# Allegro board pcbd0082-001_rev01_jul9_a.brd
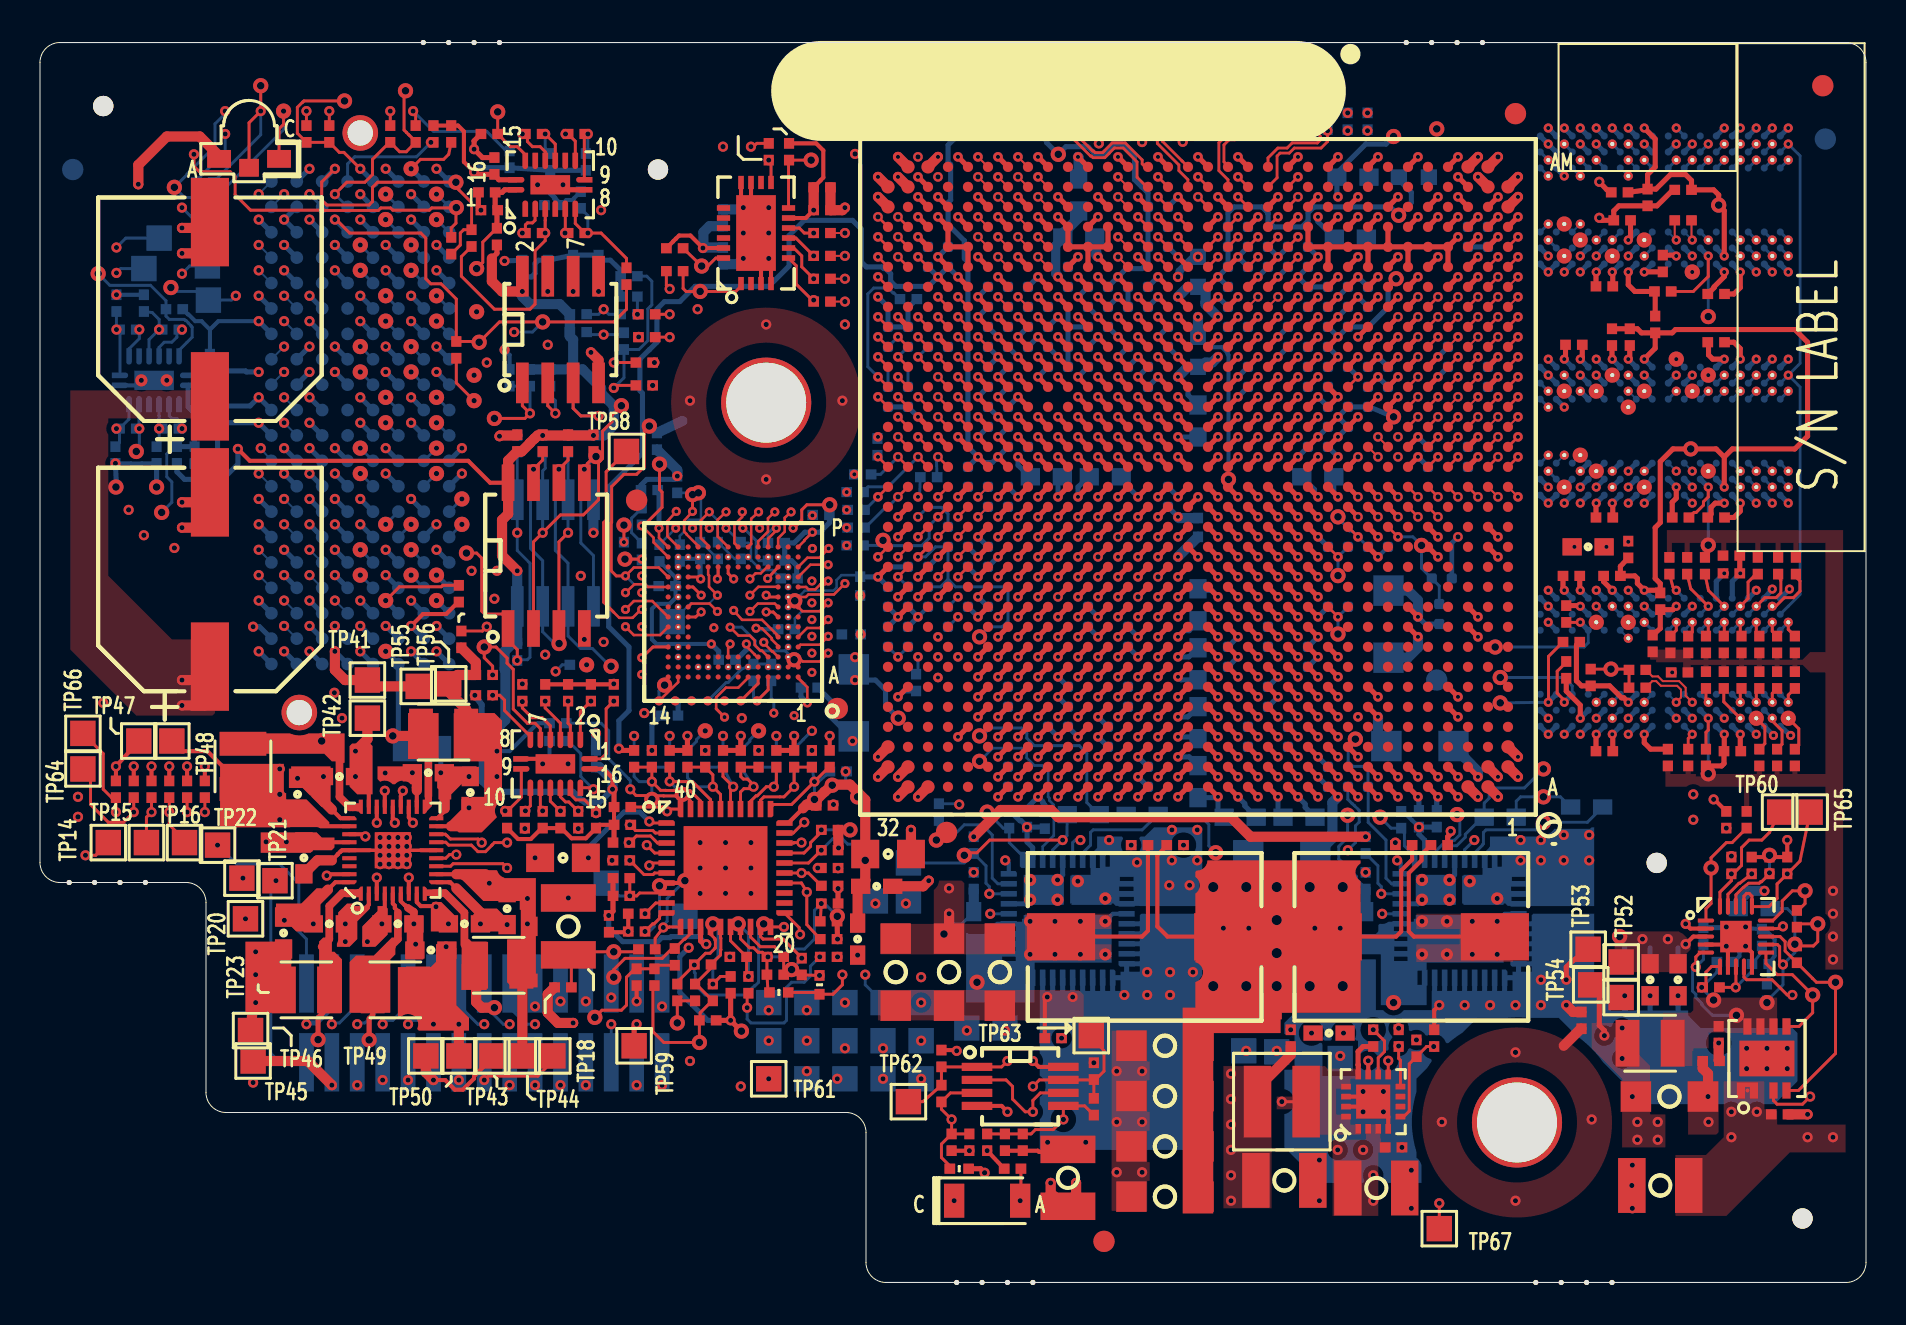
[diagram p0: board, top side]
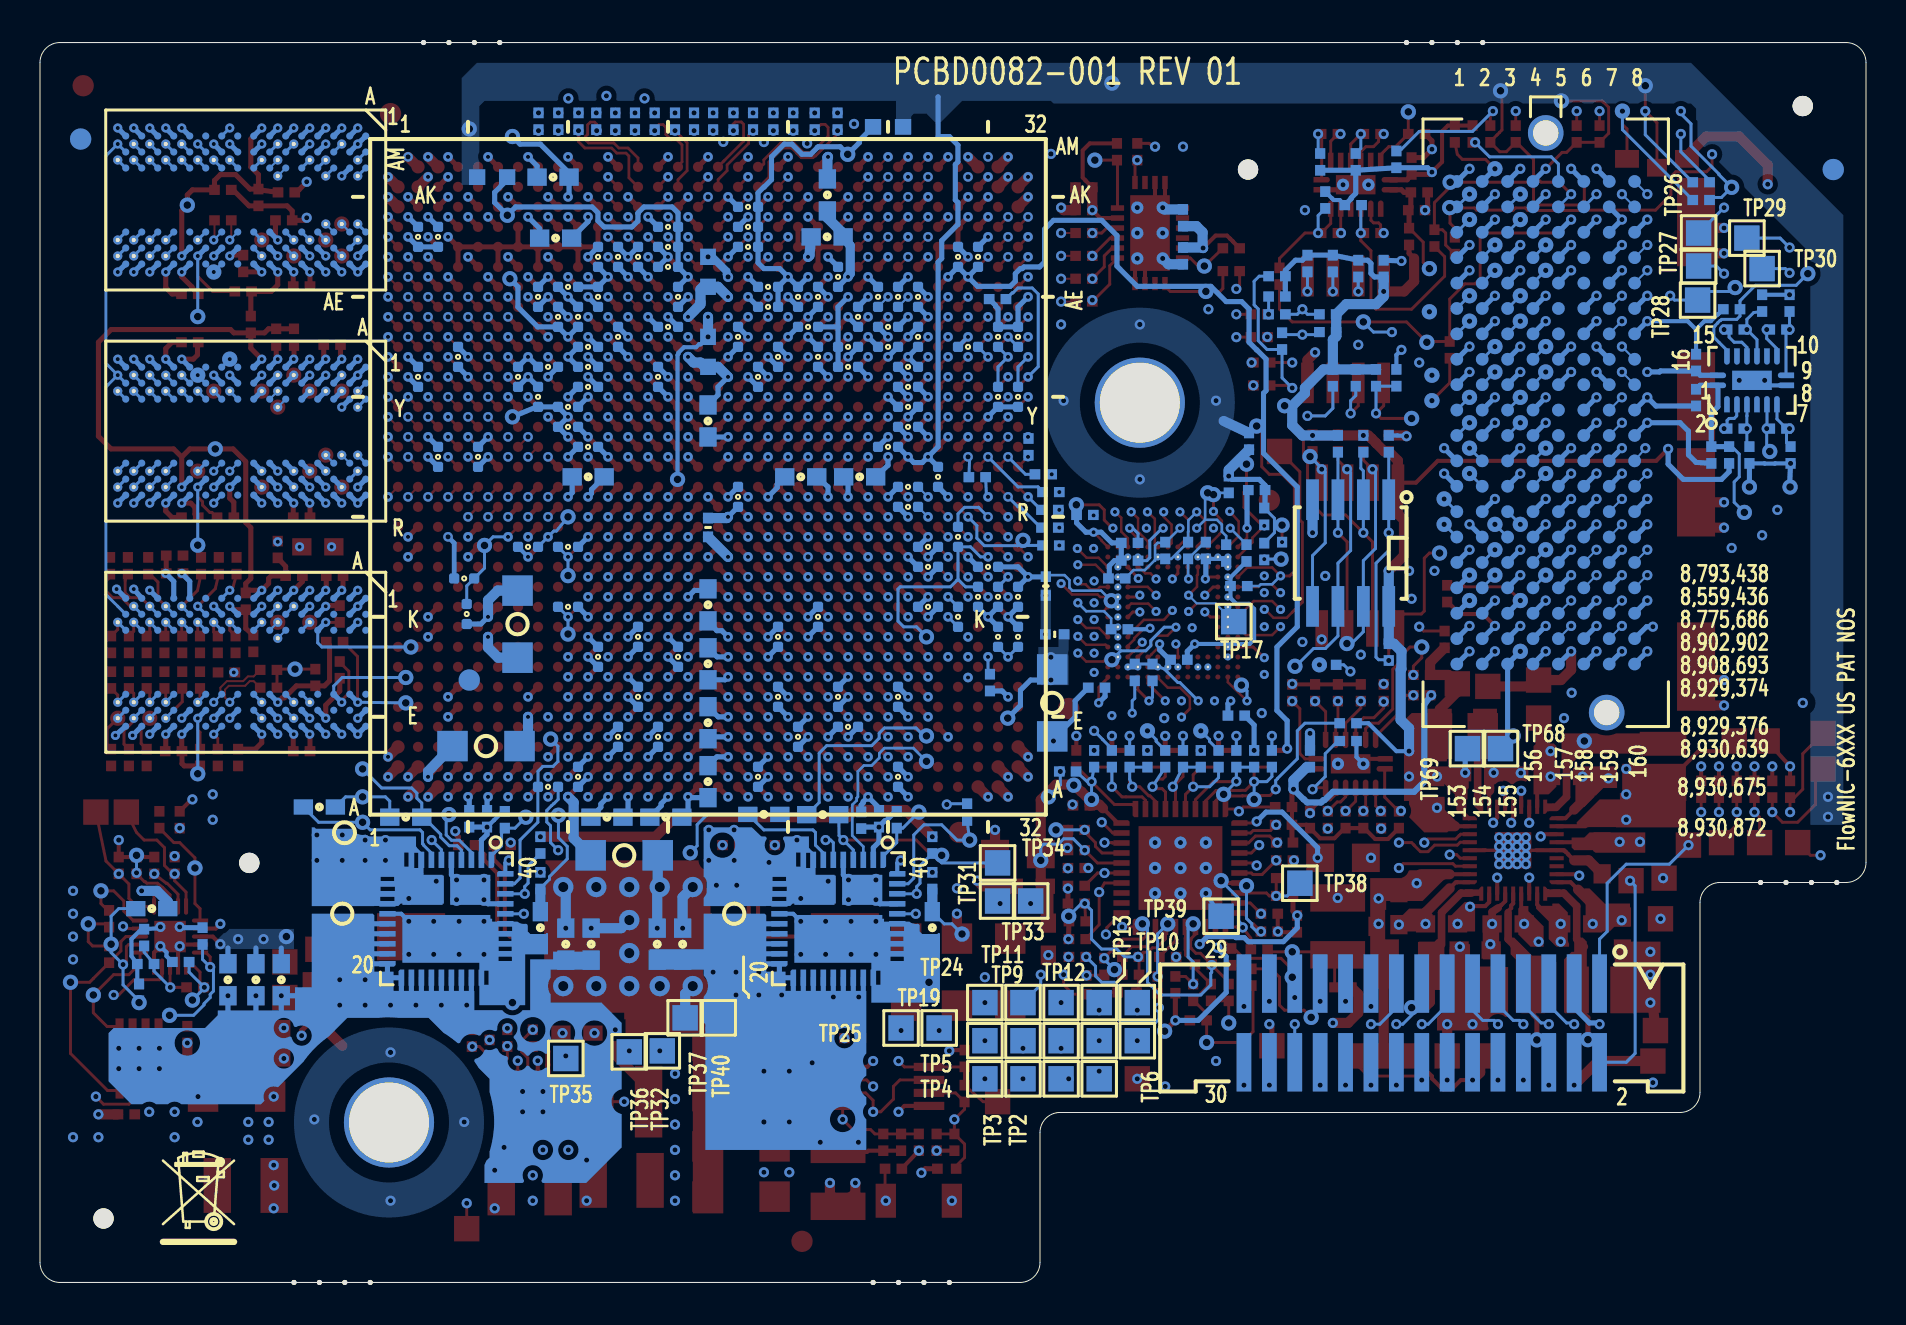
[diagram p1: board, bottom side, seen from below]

Outline 91.3 x 62 mm; copper layers: TOP, 02_GND, 03_SIG, 04_SIG, 05_GND, 06_PWR1, 07_SIG, 08_SIG, 09_GND, BOTTOM. Coordinates in mm from the lower left corner of the outline.
Outline path: 0,61 arc(0.29,61.71) 1,62 90.3,62 arc(91.01,61.71) 91.3,61 91.3,1 arc(91.01,0.29) 90.3,0 42.3,0 arc(41.59,0.29) 41.3,1 41.3,7.5 arc(41.01,8.21) 40.3,8.5 9.3,8.5 arc(8.59,8.79) 8.3,9.5 8.3,19 arc(8.01,19.71) 7.3,20 1,20 arc(0.29,20.29) 0,21 0,61

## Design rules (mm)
net group 100_OHM_DIFF_SPACE: nets PCIE0_REFCLK_N PCIE0_REFCLK_P
net group NFP_CLK_REF_: nets NFP_CLK_REF_N NFP_CLK_REF_P
net group NFP_SERDES012_SYSCLK_IN_: nets NFP_SERDES012_SYSCLK_IN_N NFP_SERDES012_SYSCLK_IN_P
net group NFP_VDD_CORE_SENSE_VDD: nets NFP_VDD_CORE_SENSE_VDD NFP_VDD_CORE_SENSE_VSS
net group 15MIL_EMPTY_SPACE_CLK: nets _NC_SPI3_SCK _NFP_ARM_SPI_FLASH_SCK _NFP_CFG_SPI_FLASH_SCK _NFP_SPI2_SCK _PSU_I2C_SCL CNTRL_SPI_SCK CPLD_PGRM_JTAG_TCK CPLD_PGRM_JTAG_TMS CPLD_SMBUS_SCL DEBUG_CPLD_PGRM_JTAG_TCK DEBUG_CPLD_PGRM_JTAG_TMS MUX_NFP_GPIO0_NWK0_I2C_SCL MUX_NFP_GPIO2_NWK1_I2C_SCL MUX_NFP_SMBUS_SCL NFP_ARM_SPI_FLASH_SCK NFP_CFG_SPI_FLASH_SCK NFP_CPLD_PRGM_JTAG_TCK NFP_CPLD_PRGM_JTAG_TMS NFP_JTAG_ARM_TCK NFP_JTAG_ARM_TMS NFP_SMBUS_SCL NFP_SPI2_SCK NWK0_I2C_SCL NWK1_I2C_SCL PGRM_JTAG_TCK PGRM_JTAG_TMS PSU_I2C_SCL SMBUS_SCL
net group 40_OHM_SE_SPACE: nets DDR0_32A_DRAMRST_L
net group 100_OHM_DIFF_PH: nets _NC_156M_N _NC_156M_P _NC_NFP_SERDES0_TX1_N _NC_NFP_SERDES0_TX1_P _NC_NFP_SERDES0_TX2_N _NC_NFP_SERDES0_TX2_P _NC_NFP_SERDES0_TX3_N _NC_NFP_SERDES0_TX3_P _NC_NFP_SERDES2_TX1_N _NC_NFP_SERDES2_TX1_P
net group POWER_PH: nets DDR_1.8V VDD_1.2V VDD_1.8V VDDA_DDR0_32B VDDA_SERDES VDDA_TS0 VDDAH_PCIE0 VDDAH_SERDES
net group PROP_DELAY_BYTE_0: nets DDR0_32A_DM0 DDR0_32A_DQ0 DDR0_32A_DQ1 DDR0_32A_DQ2 DDR0_32A_DQ3 DDR0_32A_DQ4 DDR0_32A_DQ5 DDR0_32A_DQ6 DDR0_32A_DQ7 DDR0_32A_DQS0_P
net group PROP_DELAY_BYTE_1: nets DDR0_32A_DM1 DDR0_32A_DQ8 DDR0_32A_DQ9 DDR0_32A_DQ10 DDR0_32A_DQ11 DDR0_32A_DQ12 DDR0_32A_DQ13 DDR0_32A_DQ14 DDR0_32A_DQ15 DDR0_32A_DQS1_P
net group PROP_DELAY_BYTE_2: nets DDR0_32A_DM2 DDR0_32A_DQ16 DDR0_32A_DQ17 DDR0_32A_DQ18 DDR0_32A_DQ19 DDR0_32A_DQ20 DDR0_32A_DQ21 DDR0_32A_DQ22 DDR0_32A_DQ23 DDR0_32A_DQS2_P
net group PROP_DELAY_BYTE_3: nets DDR0_32A_DM3 DDR0_32A_DQ24 DDR0_32A_DQ25 DDR0_32A_DQ26 DDR0_32A_DQ27 DDR0_32A_DQ28 DDR0_32A_DQ29 DDR0_32A_DQ30 DDR0_32A_DQ31 DDR0_32A_DQS3_P
net group PROP_DELAY_BYTE_CB: nets DDR0_32A_CB0 DDR0_32A_CB1 DDR0_32A_CB2 DDR0_32A_CB3 DDR0_32A_CB4 DDR0_32A_CB5 DDR0_32A_CB6 DDR0_32A_CB7 DDR0_32A_DM4 DDR0_32A_DQS4_P
net group PWR_SENSE_20MIL_DIFF_PH: nets NFP_VDD_CORE_ISEN1_N NFP_VDD_CORE_ISEN1_P NFP_VDD_CORE_ISEN2_N NFP_VDD_CORE_ISEN2_P
net group PWR_SENSE_SPACE: nets NFP_VDD_CORE_IMON NFP_VDD_CORE_TCOMPA NFP_VDD_CORE_TCOMPB

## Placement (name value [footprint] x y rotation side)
C1  22UF  [C_0603]  63.89 40.28 90 bottom
C2  22UF  [C_0603]  77.41 36.78 90 top
C3  22UF  [C_0603]  57.9 30.94 0 bottom
C4  22UF  [C_0603]  50.32 40.28 270 bottom
C5  22UF  [C_0603]  57.9 43.08 180 bottom
C7  22UF  [C_0603]  57.9 33.88 0 bottom
C8  10UF  [C_0402#2]  61.4 32.28 180 bottom
C9  10UF  [C_0402#2]  54.4 32.28 180 bottom
C10  22UF  [C_0603]  53.26 40.28 270 bottom
C11  22UF  [C_0603]  60.01 23.26 90 bottom
C12  22UF  [C_0603]  62.95 23.26 270 bottom
C13  22UF  [C_0603]  57.9 27.99 180 bottom
C14  22UF  [C_0603]  57.9 25.04 180 bottom
C15  22UF  [C_0603]  65.01 16.91 180 bottom
C16  22UF  [C_0603]  63.74 16.91 180 bottom
C17  22UF  [C_0603]  59.17 16.91 180 bottom
C18  22UF  [C_0603]  60.44 16.91 180 bottom
C19  22UF  [C_0603]  19.55 16.62 270 top
C20  22UF  [C_0603]  12.88 24.41 180 top
C21  22UF  [C_0603]  23.36 18.69 0 top
C22  22UF  [C_0603]  12.18 17.47 180 top
C23  22UF  [C_0603]  21.51 24.5 180 top
C24  0.01UF  [C_0402]  39.1 54.76 90 top
C25  0.01UF  [C_0402#2]  46.9 33.78 270 bottom
C26  0.01UF  [C_0402#2]  46.9 35.78 270 bottom
C27  0.01UF  [C_0402#2]  46.9 36.78 270 bottom
C28  0.01UF  [C_0402#2]  56.4 47.28 180 bottom
C29  0.01UF  [C_0402#2]  63.9 41.78 90 bottom
C30  0.01UF  [C_0402#2]  59.4 49.28 180 bottom
C31  0.01UF  [C_0402]  86.02 15.92 270 bottom
C32  0.22UF  [C_0603]  73.01 23.26 270 bottom
C33  0.22UF  [C_0603]  52.16 23.39 270 bottom
C34  6800PF  [C_0402]  36.77 15.39 90 top
C35  6800PF  [C_0402]  36.77 16.28 90 top
C36  10UF  [C_0402]  34.15 53.24 0 bottom
C37  10UF  [C_0402#2]  63.4 49.28 180 bottom
C38  10UF  [C_0402#2]  59.9 51.78 270 bottom
C39  10UF  [C_0402#2]  59.9 52.78 270 bottom
C40  10UF  [C_0402#2]  51.4 50.28 0 bottom
C41  10UF  [C_0402#2]  55.9 53.78 270 bottom
C42  10UF  [C_0402#2]  55.9 52.78 270 bottom
C43  10UF  [C_0402#2]  54.9 48.78 270 bottom
C44  10UF  [C_0402#2]  56.4 39.28 0 bottom
C46  1000PF  [C_0402]  46.68 20.09 0 bottom
C47  1000PF  [C_0402]  66.28 20.09 0 bottom
C48  1000PF  [C_0402]  31.86 14.5 0 top
C49  1000PF  [C_0402]  33.64 14.5 180 top
C50  1000PF  [C_0402]  34.91 16.28 270 top
C51  1000PF  [C_0402]  83.55 11.07 270 top
C52  68PF  [C_0402]  33.13 15.9 90 top
C57  100UF  [C_1206]  40.69 28.98 180 bottom
C58  100UF  [C_1206]  62.09 21.36 270 bottom
C59  100UF  [C_1206]  47.99 15.52 0 top
C60  100UF  [C_1206]  45.45 15.52 0 top
C61  100UF  [C_1206]  42.79 15.52 0 top
C62  100UF  [C_1206]  56.25 11.83 270 top
C63  100UF  [C_1206]  56.25 9.32 270 top
C64  100UF  [C_1206]  56.25 6.81 270 top
C65  100UF  [C_1206]  56.25 4.29 270 top
C66  100UF  [C_1206]  81.47 9.29 90 top
C67  100UF  [C_1206]  67.42 32.92 0 bottom
C68  100UF  [C_1206]  69 26.82 270 bottom
C71  8.2PF  [C_0402]  82.16 53.11 90 top
C74  4.7UF  [C_0402#2]  42.4 34.28 180 bottom
C76  4.7UF  [C_0402#2]  71.4 41.28 0 bottom
C77  4.7UF  [C_0402#2]  54.4 46.28 180 bottom
C78  4.7UF  [C_0402#2]  59.9 47.78 90 bottom
C79  4.7UF  [C_0402#2]  48.4 25.28 180 bottom
C80  4.7UF  [C_0402#2]  64.4 25.28 180 bottom
C81  680PF  [C_0402]  29.83 15.26 0 top
C82  1500PF  [C_0402]  28.45 17.93 0 top
C83  0.1UF  [C_0402]  39.1 53.62 90 top
C84  0.1UF  [C_0402]  34.15 51.33 180 bottom
C85  0.1UF  [C_0402]  24.12 50.7 0 bottom
C86  0.1UF  [C_0402#2]  43.9 35.78 270 bottom
C87  0.1UF  [C_0402]  23.86 41.97 180 top
C89  0.1UF  [C_0402#2]  62.4 51.28 0 bottom
C90  0.1UF  [C_0402#2]  61.4 51.28 0 bottom
C91  0.1UF  [C_0402#2]  59.9 50.78 270 bottom
C92  0.1UF  [C_0402#2]  50.4 48.28 180 bottom
C93  0.1UF  [C_0402#2]  50.9 46.78 90 bottom
C94  0.1UF  [C_0402#2]  52.9 47.78 270 bottom
C101  0.1UF  [C_0402#2]  55.9 51.78 270 bottom
C102  0.1UF  [C_0402#2]  54.9 49.78 270 bottom
C103  0.1UF  [C_0402#2]  53.4 49.28 180 bottom
C105  0.1UF  [C_0402]  77.53 30.25 0 top
C108  0.1UF  [C_0402]  84.57 36.35 270 top
C109  0.1UF  [C_0402]  81.98 30.5 270 top
C110  0.1UF  [C_0402]  80.63 31.95 180 top
C111  0.1UF  [C_0402]  81.39 26.25 0 top
C116  0.1UF  [C_0402#2]  65.4 48.28 0 bottom
C118  0.1UF  [C_0402]  31.48 28.34 90 bottom
C119  0.1UF  [C_0402]  39.05 38.38 90 bottom
C120  0.1UF  [C_0402]  30.47 39.62 90 bottom
C121  0.1UF  [C_0402]  38.47 29.74 270 bottom
C122  0.1UF  [C_0402]  34.35 31.14 90 bottom
C123  0.1UF  [C_0402]  27.8 26.19 0 bottom
C124  0.1UF  [C_0402]  39.23 23.85 90 top
C125  0.1UF  [C_0402]  29.07 20.22 90 top
C126  0.1UF  [C_0402]  67.68 6.75 90 top
C127  0.1UF  [C_0402]  66.66 12.22 0 top
C128  0.1UF  [C_0402]  84.26 16.03 270 bottom
C129  0.1UF  [C_0402]  87.85 16.41 0 top
C130  0.1UF  [C_0402]  86.98 8.41 90 top
C131  10UF  [C_0603]  14.47 17.93 270 top
C132  10UF  [C_0603]  21.22 17.93 90 top
C133  10UF  [C_0603]  17.89 17.93 90 top
C134  10UF  [C_0603]  14.97 25.3 270 top
C135  10UF  [C_0603]  13.2 21.23 0 top
C136  10UF  [C_0603]  81.9 15.14 180 bottom
C137  10UF  [C_0603]  80.51 15.14 180 bottom
C138  10UF  [C_0603]  81.9 15.14 0 top
C139  10UF  [C_0603]  80.51 15.14 0 top
C140  10UF  [C_0603]  79.24 15.14 180 bottom
C141  10UF  [C_0603]  19.42 25.49 90 top
C142  4.7UF  [C_0805]  26.15 21.23 270 top
C143  4.7UF  [C_0805]  42.41 21.42 90 top
C144  4.7UF  [C_1210]  26.42 17.8 90 top
C145  0.22UF  [C_0402]  57.65 58.06 0 bottom
C146  0.22UF  [C_0402]  58.6 58.06 0 bottom
C147  0.22UF  [C_0402]  56.63 58.06 0 bottom
C148  0.22UF  [C_0402]  55.65 58.06 0 bottom
C149  0.22UF  [C_0402]  54.63 58.06 0 bottom
C150  0.22UF  [C_0402]  53.64 58.06 0 bottom
C151  0.22UF  [C_0402]  52.57 58.06 0 bottom
C152  0.22UF  [C_0402]  51.42 58.06 0 bottom
C153  0.22UF  [C_0402]  65.38 58.06 0 bottom
C154  0.22UF  [C_0402]  66.38 58.06 0 bottom
C155  0.22UF  [C_0402]  63.49 58.06 0 bottom
C156  0.22UF  [C_0402]  64.38 58.06 0 bottom
C157  0.22UF  [C_0402]  62.54 58.06 0 bottom
C158  0.22UF  [C_0402]  61.55 58.06 0 bottom
C159  0.22UF  [C_0402]  60.57 58.06 0 bottom
C160  0.22UF  [C_0402]  59.55 58.06 0 bottom
C161  0.22UF  [C_0402#2]  60.4 45.28 180 bottom
C162  0.22UF  [C_0402#2]  55.4 45.28 180 bottom
C163  0.22UF  [C_0402#2]  59.4 31.28 180 bottom
C165  0.22UF  [C_0402]  83.17 17.32 0 bottom
C166  2.2UF  [C_0402#2]  62.4 47.28 180 bottom
C167  2.2UF  [C_0402#2]  48.4 29.28 180 bottom
C168  2.2UF  [C_0402#2]  62.4 27.28 180 bottom
C169  0.47UF  [C_0402#2]  63.4 51.28 0 bottom
C170  0.47UF  [C_0402#2]  64.9 49.78 270 bottom
C171  0.47UF  [C_0402#2]  52.4 49.28 180 bottom
C172  0.47UF  [C_0402#2]  50.9 45.78 90 bottom
C173  0.47UF  [C_0402#2]  55.4 25.28 180 bottom
C174  0.47UF  [C_0402#2]  53.4 27.28 180 bottom
C175  0.47UF  [C_0402#2]  52.4 33.28 0 bottom
C176  0.47UF  [C_0402#2]  50.9 27.78 90 bottom
C177  0.47UF  [C_0402#2]  63.4 31.28 180 bottom
C178  0.47UF  [C_0402#2]  52.4 46.28 180 bottom
C179  22UF  [C_1210]  76.19 18.44 270 bottom
C180  22UF  [C_1210]  56.59 18.44 270 bottom
C181  22UF  [C_1210]  62.22 5.1 0 top
C182  22UF  [C_1210]  51.4 5.23 90 top
C183  22UF  [C_1210]  66.81 4.72 0 top
C184  22UF  [C_1210]  81.01 4.85 180 top
C186  1UF  [C_0402#2]  63.9 45.78 90 bottom
C187  1UF  [C_0402#2]  64.4 48.28 0 bottom
C190  1UF  [C_0402#2]  69.4 41.28 0 bottom
C191  1UF  [C_0402#2]  72.4 52.28 0 bottom
C192  1UF  [C_0402#2]  72.4 45.28 0 bottom
C193  1UF  [C_0402#2]  70.4 46.28 0 bottom
C194  1UF  [C_0402#2]  67.4 45.28 0 bottom
C195  1UF  [C_0402#2]  66.4 49.28 0 bottom
C196  1UF  [C_0402#2]  64.9 42.78 90 bottom
C197  1UF  [C_0402#2]  54.4 29.28 180 bottom
C198  1UF  [C_0402#2]  60.4 27.28 180 bottom
C199  1UF  [C_0402#2]  61.4 29.28 180 bottom
C200  1UF  [C_0402#2]  51.4 29.28 180 bottom
C201  1UF  [C_0402]  68.95 23.19 0 bottom
C202  1UF  [C_0402]  69.84 23.19 0 bottom
C203  1UF  [C_0402]  49.35 23.19 0 bottom
C204  1UF  [C_0402]  50.24 23.11 0 bottom
C205  1UF  [C_0402]  86.35 14.5 0 bottom
C206  1UF  [C_0402]  80.38 54.25 0 top
C211  1UF  [C_0402]  83.81 49.43 270 top
C212  1UF  [C_0402]  78.22 49.81 90 top
C213  1UF  [C_0402]  81.14 50.95 180 top
C214  1UF  [C_0402]  79.11 53.11 270 top
C215  1UF  [C_0402]  83.81 38.25 270 top
C216  1UF  [C_0402]  83.81 47.01 270 top
C217  1UF  [C_0402]  76.57 35.33 90 top
C218  1UF  [C_0402]  84.62 26.57 270 top
C219  1UF  [C_0402]  78.22 26.57 90 top
C220  1UF  [C_0402]  84.57 35.46 270 top
C242  220UF  [SMC_ECE-CAP_10P2MM]  8.5 35.15 180 top
C243  220UF  [SMC_ECE-CAP_10P2MM]  8.5 48.66 180 top
C248  0.1UF  [C_0402]  46.47 7.01 0 top
C249  0.1UF  [C_0402]  49.14 7.01 0 top
C263  1UF  [C_0402]  80.76 47.9 180 top
C264  1UF  [C_0402]  81.01 34.06 0 top
C265  1UF  [C_0402]  76.7 46.89 90 top
C266  1UF  [C_0402]  78.22 38.25 90 top
C268  4.7UF  [C_0402#2]  47.9 42.78 270 bottom
C269  4.7UF  [C_0402#2]  48.9 41.78 270 bottom
C270  4.7UF  [C_0402#2]  45.4 51.28 0 bottom
C271  4.7UF  [C_0402#2]  47.9 43.78 270 bottom
C272  0.1UF  [C_0402#2]  47.9 44.78 90 bottom
C273  0.1UF  [C_0402#2]  46.4 40.28 180 bottom
C274  0.1UF  [C_0402#2]  44.4 51.28 0 bottom
C275  0.1UF  [C_0402#2]  47.9 45.78 270 bottom
C276  0.1UF  [C_0402#2]  47.4 47.28 0 bottom
C277  0.1UF  [C_0402#2]  47.4 49.28 0 bottom
C278  22UF  [C_0603]  65.52 52.22 270 bottom
C279  22UF  [C_0603]  65.65 55.27 270 bottom
C280  22UF  [C_0603]  51.93 54.38 0 bottom
C281  22UF  [C_0603]  51.94 52.28 270 bottom
C282  4.7UF  [C_0402]  22.34 54.51 270 top
C283  4.7UF  [C_0402]  8.5 44.25 180 bottom
C284  0.1UF  [C_0402]  22.72 55.83 180 top
C285  0.1UF  [C_0402]  8.5 46 0 bottom
D5  LL4148  [SOD80]  47.36 4.09 0 top
DS1  *  [APBVDA3020CGKSYKC]  10.45 56.18 180 top
J4  VAL  [CON_SAM_SEAM-20-03P5-S-08-2-A-K]  16.01 42.99 90 bottom
J5  *  [HDR_2X15_1000_240_50_SMT_SHF]  22.21 12.98 0 bottom
L1  120_100MHZ  [0603]  68.69 55.27 180 bottom
L2  120_100MHZ  [0603]  57.9 50.53 90 bottom
L3  120_100MHZ  [0603]  57.9 46.53 90 bottom
L7  0.05OHMDC_1A  [0402]  57.9 37.75 90 bottom
L9  1.0UH  [IND_SMT_2520]  80.51 11.96 180 top
L10  2.2UH  [IND_SMT_2520]  10.15 25.8 90 top
L11  2.2UH  [IND_SMT_2520]  13.32 14.63 0 top
L12  2.2UH  [IND_SMT_2520]  22.94 15.86 0 top
L13  60MOHM_1.7A  [0402]  40.56 32.41 180 bottom
L14  60MOHM_1.7A  [0402]  41.01 34.82 270 bottom
L15  120_100MHZ  [0603]  48.9 57.78 0 bottom
L17  300NH  [IND_295_425_SMT_SLC1175]  68.57 17.28 270 top
L18  300NH  [IND_295_425_SMT_SLC1175]  55.23 17.28 90 top
L19  1.0UH  [IND_SMT_2520]  17.77 14.63 180 top
L20  1.0UH  [IND_SMT_2520]  20.18 27.52 0 top
L21  3.3UH  [IND_SMT_4X4X2P1]  62.09 9.04 180 top
NOREF  -  []  91.3 -7.92 90 top
NOREF#2  -  []  -395.74 -176.46 0 top
NOREF#3  -  [unnamed#2]  53.2 2.06 0 top
NOREF#4  -  []  -0.01 69.92 0 top
NOREF#5  -  []  1 62 0 top
NOREF#6  -  []  30.54 23.43 0 top
NOREF#7  -  []  3.16 58.82 0 top
NOREF#8  -  []  3.16 58.82 0 top
NOREF#9  -  [unnamed#2]  3.16 58.82 0 top
NOREF#10  -  []  0 -7.92 0 top
NOREF#11  -  []  1.45 -17.39 0 top
NOREF#12  -  [unnamed#2]  80.84 20.98 0 top
NOREF#13  -  [unnamed#2]  89.14 59.84 0 top
NOREF#14  -  [unnamed#3]  91.3 62 0 top
NOREF#15  -  [unnamed#2]  30.9 55.65 0 top
NOREF#16  -  []  101.59 139.47 0 top
NOREF#17  -  [unnamed#2]  88.13 3.2 0 top
NOREF#18  -  []  90.3 0 90 top
NOREF#19  -  []  -395.74 -176.46 0 top
NOREF#20  -  [unnamed#4]  49.64 0 270 bottom
NOREF#21  -  [unnamed#4]  19.16 62 90 bottom
NOREF#22  -  [unnamed#4]  68.31 62 90 bottom
NOREF#23  -  [unnamed#4]  5.27 20 270 bottom
NOREF#24  -  [unnamed#2]  89.27 57.17 180 bottom
NOREF#25  -  [unnamed#2]  1.64 55.65 180 bottom
NOREF#26  -  []  58.53 99.72 180 bottom
NOREF#27  -  [unnamed#2]  69.84 30.12 180 bottom
NOREF#28  -  [unnamed#4]  78.6 0 270 bottom
Q1  *  [SON8_130_25P6_EP_Q3D]  86.35 11.2 90 top
R1  121K  [R_0402]  29.83 18.44 90 top
R2  100K  [R_0603]  64.45 12.47 90 top
R3  332K  [R_0402]  30.34 16.66 90 top
R4  30.1K  [R_0402]  86.09 17.25 180 bottom
R7  36.0  [R_0402]  79.87 29.74 270 top
R8  36.0  [R_0402]  79.87 30.63 270 top
R13  82K  [0402]  36.94 14.5 180 top
R14  4.75K  [R_0402]  37.45 56.54 0 top
R15  4.75K  [R_0402]  31.74 51.71 90 top
R16  4.75K  [R_0402#2]  44.9 46.78 270 bottom
R18  4.75K  [R_0402]  23.48 45.24 0 bottom
R19  4.75K  [R_0402#2]  43.4 34.28 0 bottom
R20  4.75K  [R_0402]  25.13 41.93 180 bottom
R21  4.75K  [R_0402]  25.13 41.97 0 top
R22  4.75K  [R_0402]  26.4 41.97 0 top
R23  4.75K  [R_0402]  27.67 41.97 0 top
R24  4.75K  [R_0402]  25.51 45.24 180 bottom
R25  4.75K  [R_0402]  25.39 50.7 180 bottom
R26  4.75K  [R_0402]  26.66 50.95 180 bottom
R27  4.75K  [R_0402]  27.93 50.95 180 bottom
R28  4.75K  [R_0402]  23.86 31.52 180 bottom
R29  4.75K  [R_0402]  26.4 41.93 180 bottom
R30  4.75K  [R_0402]  24.5 45.24 180 bottom
R31  4.75K  [R_0402]  26.66 45.24 180 bottom
R32  4.75K  [R_0402]  23.86 41.93 0 bottom
R34  4.75K  [R_0402]  21.07 32.15 0 top
R41  4.75K  [R_0402#2]  43.4 47.28 180 bottom
R42  4.75K  [R_0402#2]  42.4 47.28 180 bottom
R43  4.75K  [R_0402]  29.45 49.3 270 bottom
R44  4.75K  [R_0402]  26.91 48.41 270 bottom
R45  4.75K  [R_0402#2]  42.4 44.28 180 bottom
R46  4.75K  [R_0402#2]  43.4 44.28 180 bottom
R47  4.75K  [R_0402]  30.09 36.55 0 bottom
R48  4.75K  [R_0402]  37.33 32.66 270 bottom
R49  4.75K  [R_0402]  35.04 36.6 180 bottom
R50  4.75K  [R_0402]  37.46 35.2 90 bottom
R52  4.75K  [R_0402]  33.01 36.6 0 bottom
R53  4.75K  [R_0402]  31.99 36.47 0 bottom
R54  4.75K  [R_0402]  31.86 39.9 0 bottom
R55  4.75K  [R_0402]  33.9 36.6 0 bottom
R56  4.75K  [R_0402]  30.09 38.3 0 bottom
R57  4.75K  [R_0402]  30.98 36.47 180 bottom
R58  4.75K  [R_0402]  31.36 34.82 270 bottom
R59  4.75K  [R_0402]  25.9 27.07 90 bottom
R60  4.75K  [R_0402]  28.69 29.49 180 top
R61  4.75K  [R_0402]  26.02 23.14 180 top
R62  4.75K  [R_0402]  23.36 23.14 180 top
R63  4.75K  [R_0402]  22.21 29.36 90 top
R64  4.75K  [R_0402]  26.4 29.49 180 top
R65  4.75K  [R_0402]  27.55 29.49 180 top
R66  4.75K  [R_0402]  26.91 23.14 180 top
R67  4.75K  [R_0402]  24.24 23.14 180 top
R68  4.75K  [R_0402]  22.21 30.38 90 top
R69  4.75K  [R_0402]  27.8 23.14 180 top
R70  4.75K  [R_0402]  25.13 23.14 180 top
R71  4.75K  [R_0402]  24.12 29.49 0 top
R72  4.75K  [R_0402]  25.26 29.49 180 top
R73  4.75K  [R_0402]  20.56 57.43 0 top
R74  4.75K  [R_0402]  48.46 23.14 180 bottom
R75  4.75K  [R_0402]  66.28 21.87 0 bottom
R76  4.75K  [R_0402]  46.68 21.87 0 bottom
R77  4.75K  [R_0402]  36.82 26.19 180 top
R78  4.75K  [R_0402]  37.71 26.19 180 top
R79  4.75K  [R_0402]  39.48 26.19 180 top
R80  4.75K  [R_0402]  38.6 26.19 0 top
R81  4.75K  [R_0402]  38.6 26.19 180 bottom
R82  4.75K  [R_0402]  35.93 26.19 180 bottom
R83  4.75K  [R_0402]  30.59 26.19 0 top
R84  4.75K  [R_0402]  29.71 26.19 180 top
R85  4.75K  [R_0402]  29.07 21.99 270 top
R86  4.75K  [R_0402]  29.12 22.88 270 top
R87  4.75K  [R_0402]  29.12 23.77 270 top
R88  4.75K  [R_0402]  29.07 21.11 90 top
R89  4.75K  [R_0402]  25.9 27.96 90 bottom
R90  4.75K  [R_0402]  35.04 26.19 180 top
R91  4.75K  [R_0402]  35.93 26.19 0 top
R92  4.75K  [R_0402]  31.48 26.19 180 top
R93  4.75K  [R_0402]  32.37 26.19 180 top
R94  4.75K  [R_0402]  34.15 26.19 180 top
R95  4.75K  [R_0402]  33.26 26.19 180 bottom
R96  4.75K  [R_0402]  33.26 26.19 0 top
R97  4.75K  [R_0402]  30.59 26.19 180 bottom
R98  4.75K  [R_0402]  7.35 24.66 180 top
R99  4.75K  [R_0402]  67.93 12.22 180 top
R100  4.75K  [R_0402]  4.69 24.66 180 top
R101  4.75K  [R_0402]  45.07 11.2 0 top
R102  4.75K  [R_0402]  52.69 10.56 0 top
R103  4.75K  [R_0402]  3.8 24.66 0 top
R104  4.75K  [R_0402]  8.24 24.66 180 top
R105  4.75K  [R_0402]  87.36 20.85 0 top
R106  4.75K  [R_0402]  84.57 20.85 180 top
R107  40.2K  [R_0402]  86.47 20.85 0 top
R108  2.2  [R_0402]  87.85 18.18 0 top
R109  2.2  [R_0402]  83.93 12.39 180 top
R110  10  [R_0402]  39.48 20.72 90 top
R111  10  [R_0402]  39.43 16.28 90 top
R112  3.32K  [R_0402]  68.82 11.71 180 top
R113  732  [R_0402]  69.71 12.22 0 top
R116  2.2  [R_0603]  66.28 17.74 180 bottom
R117  2.2  [R_0603]  46.68 17.74 180 bottom
R118  2.2  [R_0603]  55.11 23.41 270 bottom
R119  2.2  [R_0603]  77.33 23.77 270 bottom
R120  100K  [R_0402]  30.72 15.26 0 top
R121  100K  [R_0402]  52.69 8.79 180 top
R122  100K  [R_0402]  45.07 9.45 180 top
R124  10K  [R_0402#2]  69.96 33.42 0 bottom
R126  10K  [R_0402]  68.06 23.14 180 bottom
R127  10K  [R_0402]  83.55 14.76 270 top
R130  2K  [R_0402]  6.46 24.66 180 top
R131  2K  [R_0402]  5.58 24.66 180 top
R132  0  [R_0402]  39.1 51.33 90 top
R133  0  [R_0402]  39.1 52.47 90 top
R134  0  [R_0402]  39.1 50.19 90 top
R135  0  [R_0402]  39.1 49.05 90 top
R138  0  [R_0402]  30.34 47.27 270 top
R139  0  [R_0402]  30.21 46 270 top
R144  0  [R_0402#2]  63.9 46.78 270 bottom
R145  0  [R_0402#2]  63.9 44.78 270 bottom
R146  0  [R_0402#2]  71.4 52.28 180 bottom
R147  0  [R_0402]  29.2 47.07 180 bottom
R148  0  [R_0402]  29.45 48.41 270 bottom
R149  0  [R_0402]  30.85 42.06 0 bottom
R152  0  [R_0402]  77.08 13.1 180 top
R159  0  [R_0402]  36.56 30.5 0 bottom
R166  0  [R_0402]  68.19 21.87 270 top
R167  0  [R_0402]  56.76 21.87 90 top
R168  0  [R_0402]  54.98 21.87 270 top
R169  0  [R_0402]  44.95 23.52 180 bottom
R170  0  [R_0402#2]  65.9 24.78 270 bottom
R171  0  [R_0402]  69.96 21.87 90 top
R172  0  [R_0402]  32.37 26.19 180 bottom
R173  0  [R_0402]  37.71 26.19 180 bottom
R174  0  [R_0402]  35.04 26.19 180 bottom
R175  0  [R_0402]  34.15 26.19 180 bottom
R176  0  [R_0402]  31.48 26.19 180 bottom
R177  0  [R_0402]  36.82 26.19 180 bottom
R178  0  [R_0402]  39.92 25.55 90 bottom
R179  0  [R_0402]  29.71 26.19 180 bottom
R180  0  [R_0402]  39.48 22.63 90 top
R181  0  [R_0402]  39.48 21.61 90 top
R182  0  [R_0402]  34.53 14.88 0 top
R186  240  [R_0402#2]  64.9 33.78 270 bottom
R187  240  [R_0402#2]  64.9 36.78 270 bottom
R188  240  [R_0402#2]  65.9 45.78 90 bottom
R189  240  [R_0402]  81.14 49.55 90 top
R199  39.0  [R_0402#2]  45.4 33.28 180 bottom
R200  39.0  [R_0402]  26.91 30.88 90 bottom
R201  39.0  [R_0402]  41.14 40.41 90 bottom
R202  39.0  [R_0402]  40.75 39.52 90 bottom
R203  39.0  [R_0402]  44.44 40.27 90 bottom
R204  39.0  [R_0402]  40.75 36.85 90 bottom
R205  39.0  [R_0402]  40.8 37.74 90 bottom
R206  39.0  [R_0402]  85.08 31.9 0 top
R207  39.0  [R_0402]  85.97 30.12 180 top
R208  39.0  [R_0402]  85.97 31.9 0 top
R209  39.0  [R_0402]  85.89 35.84 180 top
R210  39.0  [R_0402]  85.97 26.25 0 top
R211  39.0  [R_0402]  86.91 35.84 180 top
R212  39.0  [R_0402]  86.86 26.25 0 top
R213  39.0  [R_0402]  87.79 35.84 180 top
R214  39.0  [R_0402]  87.74 26.25 0 top
R215  39.0  [R_0402]  86.86 31.9 0 top
R216  39.0  [R_0402]  83.3 30.12 180 top
R217  39.0  [R_0402]  86.86 30.12 180 top
R218  39.0  [R_0402]  85.08 30.12 180 top
R219  39.0  [R_0402]  87.74 31.9 0 top
R220  39.0  [R_0402]  87.74 30.12 180 top
R222  39.0  [R_0402]  84.19 31.9 0 top
R223  39.0  [R_0402]  84.19 30.12 180 top
R224  39.0  [R_0402]  83.25 35.84 180 top
R225  39.0  [R_0402]  81.52 31.9 0 top
R226  39.0  [R_0402]  82.41 31.9 0 top
R227  39.0  [R_0402]  83.3 31.9 0 top
R229  39.0  [R_0402]  82.36 35.84 180 top
R231  39.0  [R_0402]  82.41 26.25 0 top
R262  39.0  [R_0402]  30.34 48.41 270 top
R263  39.0  [R_0402]  30.21 44.85 270 top
R264  39.0  [R_0402]  35.67 30.5 0 bottom
R267  1.5K  [R_0402]  47.36 7.01 0 top
R268  240  [R_0402]  31.74 50.57 90 top
R269  240  [R_0402]  36.44 56.54 0 top
R272  240  [R_0402#2]  70.09 35.2 270 bottom
R276  240  [R_0402]  8.24 54.13 270 bottom
R277  240  [R_0402]  8.24 55.01 270 bottom
R278  240  [R_0402]  48.63 5.69 270 top
R279  8.06K  [0402]  45.96 5.69 0 top
R281  100  [R_0402]  40.8 38.63 90 bottom
R282  100  [R_0402]  41.87 41.78 0 bottom
R283  100  [R_0402#2]  64.9 43.78 270 bottom
R284  100  [R_0402#2]  66.4 44.28 0 bottom
R285  100  [R_0402#2]  48.9 46.78 270 bottom
R286  100  [R_0402#2]  48.9 47.78 90 bottom
R287  100  [R_0402]  35.42 14.88 0 top
R288  100  [R_0402]  78.98 54.51 270 top
R289  100  [R_0402]  82.16 54.63 90 top
R308  523K  [R_0402]  29.83 17.55 90 top
R310  1.0K  [R_0402#2]  66.9 36.78 270 bottom
R312  1.0K  [R_0402]  26.15 14.76 90 top
R313  1.0K  [R_0402]  33.39 13.1 90 top
R314  1.0K  [R_0402]  39.48 19.84 90 top
R315  1.0K  [R_0402]  39.43 17.17 90 top
R316  1.0K  [R_0402]  48.25 7.01 180 top
R317  1.0K  [R_0402]  45.58 7.01 180 top
R318  1.0K  [R_0402]  85.59 20.85 0 top
R319  49.9  [R_0402#2]  49.4 49.28 180 bottom
R320  49.9  [R_0402#2]  47.9 38.78 90 bottom
R321  49.9  [R_0402#2]  47.9 39.78 90 bottom
R322  49.9  [R_0402#2]  48.4 49.28 180 bottom
R323  4.02K  [R_0402]  29.07 19.33 270 top
R324  86.6K  [R_0402]  39.43 18.06 90 top
R325  86.6K  [R_0402]  39.48 18.95 90 top
R326  4.99K  [R_0402]  31.74 16.28 0 top
R327  750  [R_0402]  38.09 15.8 0 top
R328  19.1K  [R_0402]  32.75 14.5 180 top
R329  37.4K  [0402]  38.98 14.88 270 top
R331  0  [R_0603]  85.71 18.69 270 bottom
R335  0  [R_0402]  84.32 23.14 180 top
R337  0  [R_0402]  85.33 23.14 180 top
R338  4.75K  [R_0402]  76.57 32.03 90 top
R339  4.75K  [R_0402]  76.31 30.63 180 top
R340  4.75K  [R_0402]  76.31 33.42 180 top
R350  0  [R_0402]  20.82 46.63 180 top
R351  0  [R_0402]  29.32 50.32 0 top
R352  240  [R_0402]  82.03 38.25 90 top
R353  240  [R_0402]  83.3 26.25 180 top
R354  39.0  [R_0402]  81.47 35.84 180 top
R361  100  [R_0402]  79.49 47.27 180 top
R362  100  [R_0402]  78.6 47.27 0 top
R363  100  [R_0402]  79.41 36.65 0 top
R364  100  [R_0402]  78.6 35.33 270 top
R365  4.75K  [R_0402#2]  44.4 34.28 180 bottom
R367  0  [R_0402]  13.32 57.43 0 top
R368  0  [R_0402]  14.47 57.43 0 top
R369  4.75K  [R_0402]  27.04 54.13 0 bottom
R370  4.75K  [R_0402]  27.29 56.03 180 bottom
R371  4.75K  [R_0402]  22.47 57.43 270 top
R372  4.75K  [R_0402]  22.47 53.62 270 top
R373  4.75K  [R_0402]  3.77 41.38 180 bottom
R374  4.75K  [R_0402]  3.82 48.97 0 bottom
R375  4.75K  [R_0402]  6.72 48.66 270 bottom
R376  4.75K  [R_0402]  7.73 41.38 180 bottom
R377  4.75K  [R_0402]  5.83 41.38 180 bottom
R378  4.75K  [R_0402]  5.19 48.97 0 bottom
R379  4.75K  [R_0402]  25.64 53.87 270 bottom
R380  4.75K  [R_0402]  25.51 56.03 180 bottom
R381  0  [R_0402]  24.69 52.47 270 top
R382  0  [R_0402]  26.82 52.47 270 top
R383  0  [R_0402]  26.82 57.43 270 top
R384  0  [R_0402]  24.69 57.43 270 top
R385  0  [R_0402]  6.53 42.7 270 bottom
R386  0  [R_0402]  4.39 42.7 270 bottom
R387  0  [R_0402]  4.39 47.65 270 bottom
R388  0  [R_0402]  6.53 47.65 270 bottom
R389  0  [R_0402]  17.51 57.43 0 top
R390  0  [R_0402]  18.78 57.43 0 top
R391  0  [R_0402]  21.58 52.22 180 top
R392  0  [R_0402]  20.56 51.84 0 top
R393  240  [R_0402]  22.85 52.3 0 top
R394  240  [R_0402]  6.85 41.38 180 bottom
R395  4.75K  [R_0402]  20.94 34.44 180 top
R396  4.75K  [R_0402]  19.67 57.43 0 top
R397  4.75K  [R_0402]  36.82 36.98 90 bottom
R398  4.75K  [R_0402]  36.82 36.09 90 bottom
R399  4.75K  [R_0402]  23.48 56.16 0 bottom
R400  4.75K  [R_0402]  50.66 12.22 90 top
R401  680  [R_0603]  40.88 17.17 180 top
R402  680  [R_0603]  41.83 19.81 270 top
R403  4.75K  [R_0402]  26.91 47.52 270 bottom
R404  4.75K  [R_0402]  29.45 50.32 270 bottom
R405  4.75K  [R_0402]  43.42 49.17 90 bottom
R406  4.75K  [R_0402#2]  43.4 32.28 180 bottom
R407  4.75K  [R_0402#2]  42.4 32.28 0 bottom
R408  4.75K  [R_0402]  43.8 30 180 bottom
R409  240  [R_0402#2]  45.4 37.28 0 bottom
R410  240  [R_0402]  29.2 36.6 0 bottom
R411  1.0K  [R_0402]  62.53 12.22 0 top
TP2  *  [TP50SQ_SMT]  40.25 10.18 180 bottom
TP3  *  [TP50SQ_SMT]  42.15 10.18 180 bottom
TP4  *  [TP50SQ_SMT]  44.06 10.18 180 bottom
TP5  *  [TP50SQ_SMT]  44.06 12.09 180 bottom
TP6  *  [TP50SQ_SMT]  36.44 12.09 180 bottom
TP7  *  [TP50SQ_SMT]  38.34 12.09 180 bottom
TP8  *  [TP50SQ_SMT]  40.25 12.09 180 bottom
TP9  *  [TP50SQ_SMT]  42.15 12.09 180 bottom
TP10  *  [TP50SQ_SMT]  36.44 13.99 180 bottom
TP11  *  [TP50SQ_SMT]  42.15 13.99 180 bottom
TP12  *  [TP50SQ_SMT]  40.25 13.99 180 bottom
TP13  *  [TP50SQ_SMT]  38.34 13.99 180 bottom
TP14  *  [TP50SQ_SMT]  3.42 21.99 0 top
TP15  *  [TP50SQ_SMT]  5.32 21.99 0 top
TP16  *  [TP50SQ_SMT]  7.23 21.99 0 top
TP17  *  [TP50SQ_SMT]  31.61 33.04 180 bottom
TP18  *  [TP50SQ_SMT]  25.64 11.33 0 top
TP19  *  [TP50SQ_SMT]  46.34 12.72 180 bottom
TP20  *  [TP50SQ_SMT]  10.1 20.22 0 top
TP21  *  [TP50SQ_SMT]  11.75 20.09 0 top
TP22  *  [TP50SQ_SMT]  8.88 21.87 0 top
TP23  *  [TP50SQ_SMT]  10.27 18.18 0 top
TP24  *  [TP50SQ_SMT]  44.06 13.99 180 bottom
TP25  *  [TP50SQ_SMT]  48.25 12.72 180 bottom
TP26  *  [TP50SQ_SMT]  8.37 52.47 180 bottom
TP27  *  [TP50SQ_SMT]  8.37 50.82 180 bottom
TP28  *  [TP50SQ_SMT]  8.42 49.12 180 bottom
TP29  *  [TP50SQ_SMT]  5.96 52.22 180 bottom
TP30  *  [TP50SQ_SMT]  5.19 50.7 180 bottom
TP31  *  [TP50SQ_SMT]  43.42 19.07 180 bottom
TP32  *  [TP50SQ_SMT]  60.19 11.58 180 bottom
TP33  *  [TP50SQ_SMT]  41.77 19.07 180 bottom
TP34  *  [TP50SQ_SMT]  43.42 20.98 180 bottom
TP35  *  [TP50SQ_SMT]  65.01 11.2 180 bottom
TP36  *  [TP50SQ_SMT]  61.84 11.53 270 bottom
TP37  *  [TP50SQ_SMT]  59.04 13.23 270 bottom
TP38  *  [TP50SQ_SMT]  28.31 19.96 180 bottom
TP39  *  [TP50SQ_SMT]  32.25 18.31 180 bottom
TP40  *  [TP50SQ_SMT]  57.39 13.23 180 bottom
TP41  *  [TP50SQ_SMT]  16.37 30.12 0 top
TP42  *  [TP50SQ_SMT]  16.37 28.22 0 top
TP43  *  [TP50SQ_SMT]  22.59 11.33 0 top
TP44  *  [TP50SQ_SMT]  24.12 11.33 0 top
TP45  *  [TP50SQ_SMT]  10.66 11.07 270 top
TP46  *  [TP50SQ_SMT]  10.53 12.6 0 top
TP47  *  [TP50SQ_SMT]  4.94 27.07 0 top
TP48  *  [TP50SQ_SMT]  6.59 27.07 0 top
TP49  *  [TP50SQ_SMT]  19.29 11.33 270 top
TP50  *  [TP50SQ_SMT]  20.94 11.33 180 top
TP51  *  [TP50SQ_SMT]  79.06 14.25 270 top
TP52  *  [TP50SQ_SMT]  79.06 16.03 270 top
TP53  *  [TP50SQ_SMT]  77.41 16.66 270 top
TP54  *  [TP50SQ_SMT]  77.53 14.88 270 top
TP55  *  [TP50SQ_SMT]  18.91 29.81 270 top
TP56  *  [TP50SQ_SMT]  20.43 29.93 270 top
TP57  *  [TP50SQ_SMT]  38.34 10.18 270 bottom
TP58  *  [TP50SQ_SMT]  29.32 41.55 0 top
TP59  *  [TP50SQ_SMT]  29.71 11.83 0 top
TP60  *  [TP50SQ_SMT]  86.98 23.52 0 top
TP61  *  [TP50SQ_SMT]  36.44 10.18 0 top
TP62  *  [TP50SQ_SMT]  43.42 9.04 0 top
TP63  *  [TP50SQ_SMT]  52.57 12.34 0 top
TP64  *  [TP50SQ_SMT]  2.15 25.68 0 top
TP65  *  [TP50SQ_SMT]  88.51 23.52 0 top
TP66  *  [TP50SQ_SMT]  2.15 27.46 0 top
TP67  *  [TP50SQ_SMT]  69.96 2.69 0 top
TP68  *  [TP50SQ_SMT]  18.28 26.69 180 bottom
TP69  *  [TP50SQ_SMT]  19.93 26.69 180 bottom
U1  *  [BGA1020_1MM]  57.9 40.28 180 top
U2  *  [MG132_8_8_0P5MM]  34.66 33.53 180 top
U3  *  [S-WQFN-N20]  84.8 17.3 0 top
U4  *  [MSOP8_193_25P6]  49.01 9.8 0 top
U5  *  [QFN40_236_19P7_3EP]  51.38 18.18 270 bottom
U6  *  [QFN40_236_19P7_3EP]  70.98 18.18 270 bottom
U7  *  [SO8_244_50]  25.77 36.47 270 bottom
U8  *  [SO8_244_50]  26.02 47.65 90 top
U9  VAL  [QFN36_0450X0450X0090_0040_EP-MCRL]  17.64 21.61 90 top
U10  *  [QFN40_236_19P7_EP165]  34.28 20.72 0 top
U12  *  [DHVQFN16_138_98_19P7_EP]  25.77 25.93 180 top
U13  VAL  [QFN16_0300X0300X0090_0050_EP-MCRL]  66.66 9.04 90 top
U14  *  [QFN20_197_126_19P7_EP]  35.8 52.47 90 top
U15  *  [SO8W_208MILS]  25.31 36.35 90 top
U17  -  [FBGA96]  81.01 54.13 270 bottom
U18  -  [FBGA96]  81.01 42.57 270 bottom
U19  -  [FBGA96]  81.01 31.01 270 bottom
U20  *  [DHVQFN16_138_98_19P7_EP]  25.51 54.89 0 top
U21  *  [DHVQFN16_138_98_19P7_EP]  5.7 45.11 180 bottom
V1_A-A00  -  [VPIN]  85.01 56.13 180 bottom
V1_A-A01  -  [VPIN]  85.81 52.13 180 bottom
V1_A-A02  -  [VPIN]  85.81 56.13 180 bottom
V1_A-A03  -  [VPIN]  85.01 56.93 180 bottom
V1_A-A04  -  [VPIN]  85.81 51.33 180 bottom
V1_A-A05  -  [VPIN]  85.81 56.93 180 bottom
V1_A-A06  -  [VPIN]  86.61 51.33 180 bottom
V1_A-A07  -  [VPIN]  86.61 56.93 180 bottom
V1_A-A08  -  [VPIN]  87.41 51.33 180 bottom
V1_A-A09  -  [VPIN]  86.61 56.13 180 bottom
V1_A-A10  -  [VPIN]  83.41 52.13 180 bottom
V1_A-A11  -  [VPIN]  86.61 52.13 180 bottom
V1_A-A12  -  [VPIN]  85.01 52.13 180 bottom
V1_A-A13  -  [VPIN]  87.41 56.13 180 bottom
V1_A-A14  -  [VPIN]  87.41 52.13 180 bottom
V1_A-BA0  -  [VPIN]  84.21 56.93 180 bottom
V1_A-BA1  -  [VPIN]  85.01 51.33 180 bottom
V1_A-BA2  -  [VPIN]  84.21 56.13 180 bottom
V1_A-CAS  -  [VPIN]  82.61 56.13 180 bottom
V1_A-RAS  -  [VPIN]  81.81 56.13 180 bottom
V1_A-WE  -  [VPIN]  83.41 56.13 180 bottom
V2_A-A00  -  [VPIN]  85.01 44.57 180 bottom
V2_A-A01  -  [VPIN]  85.81 40.57 180 bottom
V2_A-A02  -  [VPIN]  85.81 44.57 180 bottom
V2_A-A03  -  [VPIN]  85.01 45.37 180 bottom
V2_A-A04  -  [VPIN]  85.81 39.77 180 bottom
V2_A-A05  -  [VPIN]  85.81 45.37 180 bottom
V2_A-A06  -  [VPIN]  86.61 39.77 180 bottom
V2_A-A07  -  [VPIN]  86.61 45.37 180 bottom
V2_A-A08  -  [VPIN]  87.41 39.77 180 bottom
V2_A-A09  -  [VPIN]  86.61 44.57 180 bottom
V2_A-A10  -  [VPIN]  83.41 40.57 0 top
V2_A-A11  -  [VPIN]  86.61 40.57 180 bottom
V2_A-A12  -  [VPIN]  85.01 40.57 180 bottom
V2_A-A13  -  [VPIN]  87.41 44.57 180 bottom
V2_A-A14  -  [VPIN]  87.41 40.57 180 bottom
V2_A-BA0  -  [VPIN]  84.21 45.37 180 bottom
V2_A-BA1  -  [VPIN]  85.01 39.77 180 bottom
V2_A-BA2  -  [VPIN]  84.21 44.57 180 bottom
V2_A-CAS  -  [VPIN]  82.61 44.57 0 top
V2_A-RAS  -  [VPIN]  81.81 44.57 180 bottom
V2_A-WE  -  [VPIN]  83.41 44.57 180 bottom
V3_A-A00  -  [VPIN]  85.01 33.01 180 bottom
V3_A-A01  -  [VPIN]  85.81 29.01 180 bottom
V3_A-A02  -  [VPIN]  85.81 33.01 180 bottom
V3_A-A03  -  [VPIN]  85.01 33.81 180 bottom
V3_A-A04  -  [VPIN]  85.81 28.21 0 top
V3_A-A05  -  [VPIN]  85.81 33.81 180 bottom
V3_A-A06  -  [VPIN]  86.61 28.21 180 bottom
V3_A-A07  -  [VPIN]  86.61 33.81 180 bottom
V3_A-A08  -  [VPIN]  87.41 28.21 0 top
V3_A-A09  -  [VPIN]  86.61 33.01 180 bottom
V3_A-A10  -  [VPIN]  83.41 29.01 180 bottom
V3_A-A11  -  [VPIN]  86.61 29.01 180 bottom
V3_A-A12  -  [VPIN]  85.01 29.01 180 bottom
V3_A-A13  -  [VPIN]  87.41 33.01 180 bottom
V3_A-A14  -  [VPIN]  87.41 29.01 180 bottom
V3_A-BA0  -  [VPIN]  84.21 33.81 180 bottom
V3_A-BA1  -  [VPIN]  85.01 28.21 180 bottom
V3_A-BA2  -  [VPIN]  84.21 33.01 180 bottom
V3_A-CAS  -  [VPIN]  82.61 33.01 180 bottom
V3_A-RAS  -  [VPIN]  81.81 33.01 180 bottom
V3_A-WE  -  [VPIN]  83.41 33.01 180 bottom
V_A-CB0  -  [VPIN]  78.61 33.81 180 bottom
V_A-CB1  -  [VPIN]  80.21 29.01 180 bottom
V_A-CB2  -  [VPIN]  77.81 33.01 0 top
V_A-CB3  -  [VPIN]  80.21 28.21 180 bottom
V_A-CB4  -  [VPIN]  78.61 28.21 180 bottom
V_A-CB5  -  [VPIN]  78.61 29.01 180 bottom
V_A-CB6  -  [VPIN]  79.41 33.81 180 bottom
V_A-CB7  -  [VPIN]  80.21 33.01 180 bottom
V_A-DM0  -  [VPIN]  77.81 52.13 180 bottom
V_A-DM1  -  [VPIN]  77.01 56.13 180 bottom
V_A-DM2  -  [VPIN]  77.81 40.57 0 top
V_A-DM3  -  [VPIN]  77.01 44.57 180 bottom
V_A-DM4  -  [VPIN]  77.81 29.01 180 bottom
V_A-DQ00  -  [VPIN]  78.61 56.93 180 bottom
V_A-DQ01  -  [VPIN]  79.41 56.93 180 bottom
V_A-DQ02  -  [VPIN]  80.21 51.33 180 bottom
V_A-DQ03  -  [VPIN]  80.21 52.13 0 top
V_A-DQ04  -  [VPIN]  80.21 56.13 180 bottom
V_A-DQ05  -  [VPIN]  77.81 56.13 180 bottom
V_A-DQ06  -  [VPIN]  78.61 52.13 180 bottom
V_A-DQ07  -  [VPIN]  78.61 51.33 0 top
V_A-DQ08  -  [VPIN]  77.01 52.13 0 top
V_A-DQ09  -  [VPIN]  77.01 55.33 180 bottom
V_A-DQ10  -  [VPIN]  76.21 51.33 0 top
V_A-DQ11  -  [VPIN]  75.41 52.13 180 bottom
V_A-DQ12  -  [VPIN]  75.41 56.13 180 bottom
V_A-DQ13  -  [VPIN]  75.41 52.93 180 bottom
V_A-DQ14  -  [VPIN]  75.41 55.33 180 bottom
V_A-DQ15  -  [VPIN]  76.21 56.93 180 bottom
V_A-DQ16  -  [VPIN]  77.81 44.57 0 top
V_A-DQ17  -  [VPIN]  79.41 45.37 180 bottom
V_A-DQ18  -  [VPIN]  78.61 40.57 180 bottom
V_A-DQ19  -  [VPIN]  80.21 44.57 0 top
V_A-DQ20  -  [VPIN]  78.61 39.77 180 bottom
V_A-DQ21  -  [VPIN]  78.61 45.37 0 top
V_A-DQ22  -  [VPIN]  80.21 39.77 0 top
V_A-DQ23  -  [VPIN]  80.21 40.57 180 bottom
V_A-DQ24  -  [VPIN]  75.41 44.57 180 bottom
V_A-DQ25  -  [VPIN]  76.21 39.77 0 top
V_A-DQ26  -  [VPIN]  75.41 41.37 180 bottom
V_A-DQ27  -  [VPIN]  77.01 40.57 180 bottom
V_A-DQ28  -  [VPIN]  75.41 40.57 180 bottom
V_A-DQ29  -  [VPIN]  75.41 43.77 180 bottom
V_A-DQ30  -  [VPIN]  76.21 44.57 0 top
V_A-DQ31  -  [VPIN]  76.21 45.37 180 bottom
V_A-DQS0-N  -  [VPIN]  79.41 56.13 180 bottom
V_A-DQS0-P  -  [VPIN]  79.41 55.33 180 bottom
V_A-DQS1-N  -  [VPIN]  76.21 52.93 0 top
V_A-DQS1-P  -  [VPIN]  77.01 52.93 180 bottom
V_A-DQS2-N  -  [VPIN]  79.41 44.57 180 bottom
V_A-DQS2-P  -  [VPIN]  79.41 43.77 0 top
V_A-DQS3-N  -  [VPIN]  76.21 41.37 180 bottom
V_A-DQS3-P  -  [VPIN]  77.01 41.37 0 top
V_A-DQS4-N  -  [VPIN]  79.41 33.01 0 top
V_A-DQS4-P  -  [VPIN]  79.41 32.21 180 bottom

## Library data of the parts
C1-C5 C7 C10-C23 C278-C281 = CAPC0063: User Part Number: *; Tolerance: *
C8 C9 C37-C44 = CAPC0064: alternate symbols: (0402_1MM)
C24 C31 = CAPC1553: Tolerance: *; User Part Number: *; alternate symbols: (0402_1MM)
C25-C30 = CAPC1553: alternate symbols: (0402_1MM)
C32 C33 = CAPC0022: User Part Number: *; Tolerance: *
C34 C35 = CAPC0079: Tolerance: *; User Part Number: *; room: FTDI_SPI_JTAG
C36 = CAPC0064: Tolerance: *; User Part Number: *; alternate symbols: (0402_1MM)
C46-C51 = CAPC0083: Tolerance: *; User Part Number: *; alternate symbols: (0402_1MM)
C52 = CAPC0030: Tolerance: *; User Part Number: *
C57-C68 = CAPC0087: Tolerance: *; User Part Number: *
C71 = CAPC0004: Tolerance: *; User Part Number: *; alternate symbols: (0402_1MM)
C74 C76-C80 C268-C271 = CAPC0065: alternate symbols: (0402_1MM)
C81 = CAPC0012: Tolerance: *; User Part Number: *; alternate symbols: (0402_1MM)
C82 = CAPC0088: Tolerance: *; User Part Number: *; alternate symbols: (0402_1MM)
C83-C85 C87 C105 C108-C111 C118-C130 C248 C249 C284 C285 = CAPC0073: Tolerance: *; User Part Number: *; alternate symbols: (0402_1MM)
C86 C89-C94 C101-C103 C116 C272-C277 = CAPC0073: alternate symbols: (0402_1MM)
C131-C141 = CAPC0058: User Part Number: *; Tolerance: *
C142 C143 = CAPC0029: User Part Number: *; Tolerance: *
C144 = CAPC0024
C145-C160 = CAPC0062: Tolerance: *; User Part Number: *; alternate symbols: (0402_1MM); signal model: CAPC0062_0.22UF
C161-C163 = CAPC0062: alternate symbols: (0402_1MM)
C165 = CAPC0062: Tolerance: *; User Part Number: *; alternate symbols: (0402_1MM)
C166-C168 = CAPC0066: alternate symbols: (0402_1MM)
C169-C178 = CAPC0047: alternate symbols: (0402_1MM)
C179-C184 = CAPC0009
C186 C187 C190-C200 = CAPC0028: alternate symbols: (0402_1MM)
C201-C206 C211-C220 C263-C266 = CAPC0028: Tolerance: *; User Part Number: *; alternate symbols: (0402_1MM)
C242 C243 = CAPE0005: Tolerance: *; User Part Number: *
C282 C283 = CAPC0065: Tolerance: *; User Part Number: *; alternate symbols: (0402_1MM)
D5 = DIOD0001V: Tolerance: *; User Part Number: *
DS1 = LEDS0007
J4 = CONM0071: User Part Number: PN; Tolerance: TOL
J5 = CONM0077
L1 L2 L15 = INDS0021
L3 = INDS0021: room: FTDI_SPI_JTAG
L7 = INDS0010
L9 L19 L20 = INDS0061: Tolerance: *; User Part Number: *
L10-L12 = INDS0060: Tolerance: *; User Part Number: *
L13 L14 = INDS0015: alternate symbols: (0402_1MM)
L17 L18 = INDS0042: Tolerance: *; User Part Number: *
L21 = INDS0062: Tolerance: *; User Part Number: *
Q1 = TRAN0028
R1 = REST0174: Tolerance: *; User Part Number: *; alternate symbols: (0402_1MM)
R2 = REST0288: User Part Number: *; Tolerance: *
R3 = REST0121: Tolerance: *; User Part Number: *; alternate symbols: (0402_1MM)
R4 = REST0216: Tolerance: *; User Part Number: *
R7 R8 = REST0125: Tolerance: *; User Part Number: *; alternate symbols: (0402_1MM)
R13 = REST0239
R14 R18 R20-R32 R34 R43 R44 R47-R50 R52-R106 R338-R340 R369-R380 R395-R400 R403-R405 R408 = REST4024: Tolerance: *; User Part Number: *; alternate symbols: (0402_1MM)
R15 = REST4024: Tolerance: *; User Part Number: *; alternate symbols: (0402_1MM); room: FTDI_SPI_JTAG
R16 R19 R41 R42 R45 R46 R365 R406 R407 = REST4024: alternate symbols: (0402_1MM)
R107 = REST0171: Tolerance: *; User Part Number: *; alternate symbols: (0402_1MM)
R108 R109 = REST0114: Tolerance: *; User Part Number: *; alternate symbols: (0402_1MM)
R110 R111 = REST0076: Tolerance: *; User Part Number: *; alternate symbols: (0402_1MM)
R112 = REST0061: Tolerance: *; User Part Number: *; alternate symbols: (0402_1MM)
R113 = REST0289: Tolerance: *; User Part Number: *
R116-R119 = REST0145: User Part Number: *; Tolerance: *
R120-R122 = REST0001: Tolerance: *; User Part Number: *; alternate symbols: (0402_1MM)
R124 = REST0005: alternate symbols: (0402_1MM)
R126 R127 = REST0005: Tolerance: *; User Part Number: *; alternate symbols: (0402_1MM)
R130 R131 = REST0138: Tolerance: *; User Part Number: *; alternate symbols: (0402_1MM)
R132-R135 R138 R139 R147-R149 R152 R159 R166-R169 R171-R182 R335 R337 R350 R351 R367 R368 R381-R392 = REST1111: Tolerance: *; User Part Number: *; alternate symbols: (0402_1MM)
R144-R146 R170 = REST1111: alternate symbols: (0402_1MM)
R186-R188 R272 R409 = REST0009: alternate symbols: (0402_1MM)
R189 R268 R269 R276-R278 R352 R353 R393 R394 R410 = REST0009: Tolerance: *; User Part Number: *; alternate symbols: (0402_1MM)
R199 = REST0108: alternate symbols: (0402_1MM)
R200-R220 R222-R227 R229 R231 R262-R264 R354 = REST0108: Tolerance: *; User Part Number: *; alternate symbols: (0402_1MM)
R267 = REST0055: Tolerance: *; User Part Number: *; alternate symbols: (0402_1MM)
R279 = REST0211
R281 R282 R287-R289 R361-R364 = REST4030: Tolerance: *; User Part Number: *; alternate symbols: (0402_1MM)
R283-R286 = REST4030: alternate symbols: (0402_1MM)
R308 = REST0291: Tolerance: *; User Part Number: *; alternate symbols: (0402_1MM)
R310 = REST0025: alternate symbols: (0402_1MM)
R312-R318 R411 = REST0025: Tolerance: *; User Part Number: *; alternate symbols: (0402_1MM)
R319-R322 = REST0048: alternate symbols: (0402_1MM)
R323 = REST0067: Tolerance: *; User Part Number: *; alternate symbols: (0402_1MM)
R324 R325 = REST0029: Tolerance: *; User Part Number: *; alternate symbols: (0402_1MM)
R326 = REST0014: Tolerance: *; User Part Number: *; alternate symbols: (0402_1MM)
R327 = REST0185: Tolerance: *; User Part Number: *; alternate symbols: (0402_1MM)
R328 = REST0018: Tolerance: *; User Part Number: *; alternate symbols: (0402_1MM)
R329 = REST0227
R331 = REST1010: User Part Number: *; Tolerance: *
R401 R402 = REST0283: User Part Number: *; Tolerance: *
TP2-TP69 = TP_SMALL
U1 = ICBG0048: alternate symbols: (BGA1020_1MM_SKT,BGA1020_1MM_LCSKT)
U2 = PROG0057
U3 = DCDC0049
U4 = ICSO0127
U5 U6 = TRAN0026
U7 U8 = PROG0053
U9 = DCDC0065: User Part Number: PN; Tolerance: TOL
U10 = ICSO0124
U12 U20 U21 = ICSO0128
U13 = DCDC0066: Tolerance: TOL; User Part Number: PN
U14 = ICSO0125
U15 = PROG0055
U17-U19 = MEMC0051
V1_A-A00 V1_A-A01 V1_A-A02 V1_A-A03 V1_A-A04 V1_A-A05 V1_A-A06 V1_A-A07 V1_A-A08 V1_A-A09-V1_A-A14 V1_A-BA0-V1_A-BA2 V1_A-CAS V1_A-RAS V1_A-WE = VPIN_R1
V2_A-A00 V2_A-A01 V2_A-A02 V2_A-A03 V2_A-A04 V2_A-A05 V2_A-A06 V2_A-A07 V2_A-A08 V2_A-A09-V2_A-A14 V2_A-BA0-V2_A-BA2 V2_A-CAS V2_A-RAS V2_A-WE = VPIN_R2
V3_A-A00 V3_A-A01 V3_A-A02 V3_A-A03 V3_A-A04 V3_A-A05 V3_A-A06 V3_A-A07 V3_A-A08 V3_A-A09-V3_A-A14 V3_A-BA0-V3_A-BA2 V3_A-CAS V3_A-RAS V3_A-WE = VPIN_R3
V_A-CB0-V_A-CB7 V_A-DM0-V_A-DM4 V_A-DQ00 V_A-DQ01 V_A-DQ02 V_A-DQ03 V_A-DQ04 V_A-DQ05 V_A-DQ06 V_A-DQ07 V_A-DQ08 V_A-DQ09-V_A-DQ31 V_A-DQS0-N V_A-DQS0-P V_A-DQS1-N V_A-DQS1-P V_A-DQS2-N V_A-DQS2-P V_A-DQS3-N V_A-DQS3-P V_A-DQS4-N V_A-DQS4-P = VPIN_3

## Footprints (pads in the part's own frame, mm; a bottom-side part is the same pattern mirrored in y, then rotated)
0402
  rect 0.533x0.508 smd: 1(-0.47,0) 2(0.47,0)
0603
  rect 0.813x0.787 smd: 1(-0.749,0) 2(0.749,0)
APBVDA3020CGKSYKC
  rect 1.194x0.889 smd: 1(1.499,0) 3(-1.499,0)
  rect 0.991x0.889 smd: 2(0,0.445)
BGA1020_1MM
  round 1.067 smd: (-15.875,-18.161) (12.573,17.78)
  round 0.66 smd: A2(-14.5,15.5) A3(-13.5,15.5) A30(13.5,15.5) A31(14.5,15.5) AK1(-15.5,-13.5) AK32(15.5,-13.5) AL1(-15.5,-14.5) AL2(-14.5,-14.5) AL31(14.5,-14.5) AL32(15.5,-14.5) AM2(-14.5,-15.5) AM3(-13.5,-15.5) AM30(13.5,-15.5) AM31(14.5,-15.5) B1(-15.5,14.5) B2(-14.5,14.5) B31(14.5,14.5) B32(15.5,14.5) C1(-15.5,13.5) C32(15.5,13.5)
  round 0.508 smd: A4(-12.5,15.5) A5(-11.5,15.5) A6(-10.5,15.5) A7(-9.5,15.5) A8(-8.5,15.5) A9(-7.5,15.5) A10(-6.5,15.5) A11(-5.5,15.5) A12(-4.5,15.5) A13(-3.5,15.5) A14(-2.5,15.5) A15(-1.5,15.5) A16(-0.5,15.5) A17(0.5,15.5) A18(1.5,15.5) A19(2.5,15.5) A20(3.5,15.5) A21(4.5,15.5) A22(5.5,15.5) A23(6.5,15.5) A24(7.5,15.5) A25(8.5,15.5) A26(9.5,15.5) A27(10.5,15.5) A28(11.5,15.5) A29(12.5,15.5) AA1(-15.5,-4.5) AA2(-14.5,-4.5) AA3(-13.5,-4.5) AA4(-12.5,-4.5) AA5(-11.5,-4.5) AA6(-10.5,-4.5) AA7(-9.5,-4.5) AA8(-8.5,-4.5) AA9(-7.5,-4.5) AA10(-6.5,-4.5) AA11(-5.5,-4.5) AA12(-4.5,-4.5) AA13(-3.5,-4.5) AA14(-2.5,-4.5) AA15(-1.5,-4.5) AA16(-0.5,-4.5) AA17(0.5,-4.5) AA18(1.5,-4.5) AA19(2.5,-4.5) AA20(3.5,-4.5) AA21(4.5,-4.5) AA22(5.5,-4.5) AA23(6.5,-4.5) AA24(7.5,-4.5) AA25(8.5,-4.5) AA26(9.5,-4.5) AA27(10.5,-4.5) AA28(11.5,-4.5) AA29(12.5,-4.5) AA30(13.5,-4.5) AA31(14.5,-4.5) AA32(15.5,-4.5) AB1(-15.5,-5.5) AB2(-14.5,-5.5) AB3(-13.5,-5.5) AB4(-12.5,-5.5) AB5(-11.5,-5.5) AB6(-10.5,-5.5) AB7(-9.5,-5.5) AB8(-8.5,-5.5) AB9(-7.5,-5.5) AB10(-6.5,-5.5) AB11(-5.5,-5.5) AB12(-4.5,-5.5) AB13(-3.5,-5.5) AB14(-2.5,-5.5) AB15(-1.5,-5.5) AB16(-0.5,-5.5) AB17(0.5,-5.5) AB18(1.5,-5.5) AB19(2.5,-5.5) AB20(3.5,-5.5) AB21(4.5,-5.5) AB22(5.5,-5.5) AB23(6.5,-5.5) AB24(7.5,-5.5) AB25(8.5,-5.5) AB26(9.5,-5.5) AB27(10.5,-5.5) AB28(11.5,-5.5) AB29(12.5,-5.5) AB30(13.5,-5.5) AB31(14.5,-5.5) AB32(15.5,-5.5) AC1(-15.5,-6.5) AC2(-14.5,-6.5) AC3(-13.5,-6.5) AC4(-12.5,-6.5) AC5(-11.5,-6.5) AC6(-10.5,-6.5) AC7(-9.5,-6.5) AC8(-8.5,-6.5) AC9(-7.5,-6.5) AC10(-6.5,-6.5) AC11(-5.5,-6.5) AC12(-4.5,-6.5) AC13(-3.5,-6.5) AC14(-2.5,-6.5) AC15(-1.5,-6.5) AC16(-0.5,-6.5) AC17(0.5,-6.5) AC18(1.5,-6.5) AC19(2.5,-6.5) AC20(3.5,-6.5) AC21(4.5,-6.5) AC22(5.5,-6.5) AC23(6.5,-6.5) AC24(7.5,-6.5) AC25(8.5,-6.5) AC26(9.5,-6.5) AC27(10.5,-6.5) AC28(11.5,-6.5) AC29(12.5,-6.5) AC30(13.5,-6.5) AC31(14.5,-6.5) AC32(15.5,-6.5) AD1(-15.5,-7.5) AD2(-14.5,-7.5) AD3(-13.5,-7.5) AD4(-12.5,-7.5) AD5(-11.5,-7.5) AD6(-10.5,-7.5) AD7(-9.5,-7.5) AD8(-8.5,-7.5) AD9(-7.5,-7.5) AD10(-6.5,-7.5) AD11(-5.5,-7.5) AD12(-4.5,-7.5) AD13(-3.5,-7.5) AD14(-2.5,-7.5) AD15(-1.5,-7.5) AD16(-0.5,-7.5) AD17(0.5,-7.5) AD18(1.5,-7.5) AD19(2.5,-7.5) AD20(3.5,-7.5) AD21(4.5,-7.5) AD22(5.5,-7.5) AD23(6.5,-7.5) AD24(7.5,-7.5) AD25(8.5,-7.5) AD26(9.5,-7.5) AD27(10.5,-7.5) AD28(11.5,-7.5) AD29(12.5,-7.5) AD30(13.5,-7.5) AD31(14.5,-7.5) AD32(15.5,-7.5) AE1(-15.5,-8.5) AE2(-14.5,-8.5) AE3(-13.5,-8.5) AE4(-12.5,-8.5) AE5(-11.5,-8.5) AE6(-10.5,-8.5) AE7(-9.5,-8.5) AE8(-8.5,-8.5) AE9(-7.5,-8.5) AE10(-6.5,-8.5) AE11(-5.5,-8.5) AE12(-4.5,-8.5) AE13(-3.5,-8.5) AE14(-2.5,-8.5) AE15(-1.5,-8.5) AE16(-0.5,-8.5) AE17(0.5,-8.5) AE18(1.5,-8.5) AE19(2.5,-8.5) AE20(3.5,-8.5) AE21(4.5,-8.5) AE22(5.5,-8.5) AE23(6.5,-8.5) AE24(7.5,-8.5) AE25(8.5,-8.5) AE26(9.5,-8.5) AE27(10.5,-8.5) AE28(11.5,-8.5) AE29(12.5,-8.5) AE30(13.5,-8.5) AE31(14.5,-8.5) AE32(15.5,-8.5) AF1(-15.5,-9.5) AF2(-14.5,-9.5) AF3(-13.5,-9.5) AF4(-12.5,-9.5) AF5(-11.5,-9.5) AF6(-10.5,-9.5) AF7(-9.5,-9.5) AF8(-8.5,-9.5) AF9(-7.5,-9.5) AF10(-6.5,-9.5) AF11(-5.5,-9.5) AF12(-4.5,-9.5) AF13(-3.5,-9.5) AF14(-2.5,-9.5) AF15(-1.5,-9.5) AF16(-0.5,-9.5) AF17(0.5,-9.5) AF18(1.5,-9.5) AF19(2.5,-9.5) AF20(3.5,-9.5) AF21(4.5,-9.5) AF22(5.5,-9.5) AF23(6.5,-9.5) AF24(7.5,-9.5) AF25(8.5,-9.5) AF26(9.5,-9.5) AF27(10.5,-9.5) AF28(11.5,-9.5) AF29(12.5,-9.5) AF30(13.5,-9.5) AF31(14.5,-9.5) AF32(15.5,-9.5) AG1(-15.5,-10.5) AG2(-14.5,-10.5) AG3(-13.5,-10.5) AG4(-12.5,-10.5) AG5(-11.5,-10.5) AG6(-10.5,-10.5) AG7(-9.5,-10.5) AG8(-8.5,-10.5) AG9(-7.5,-10.5) AG10(-6.5,-10.5) AG11(-5.5,-10.5) AG12(-4.5,-10.5) AG13(-3.5,-10.5) AG14(-2.5,-10.5) AG15(-1.5,-10.5) AG16(-0.5,-10.5) AG17(0.5,-10.5) AG18(1.5,-10.5) AG19(2.5,-10.5) AG20(3.5,-10.5) AG21(4.5,-10.5) AG22(5.5,-10.5) AG23(6.5,-10.5) AG24(7.5,-10.5) AG25(8.5,-10.5) AG26(9.5,-10.5) AG27(10.5,-10.5) AG28(11.5,-10.5) AG29(12.5,-10.5) AG30(13.5,-10.5) AG31(14.5,-10.5) AG32(15.5,-10.5) AH1(-15.5,-11.5) AH2(-14.5,-11.5) AH3(-13.5,-11.5) AH4(-12.5,-11.5) AH5(-11.5,-11.5) AH6(-10.5,-11.5) AH7(-9.5,-11.5) AH8(-8.5,-11.5) AH9(-7.5,-11.5) AH10(-6.5,-11.5) AH11(-5.5,-11.5) AH12(-4.5,-11.5) AH13(-3.5,-11.5) AH14(-2.5,-11.5) AH15(-1.5,-11.5) AH16(-0.5,-11.5) AH17(0.5,-11.5) AH18(1.5,-11.5) AH19(2.5,-11.5) AH20(3.5,-11.5) AH21(4.5,-11.5) AH22(5.5,-11.5) AH23(6.5,-11.5) AH24(7.5,-11.5) AH25(8.5,-11.5) AH26(9.5,-11.5) AH27(10.5,-11.5) AH28(11.5,-11.5) AH29(12.5,-11.5) AH30(13.5,-11.5) AH31(14.5,-11.5) AH32(15.5,-11.5) AJ1(-15.5,-12.5) AJ2(-14.5,-12.5) AJ3(-13.5,-12.5) AJ4(-12.5,-12.5) AJ5(-11.5,-12.5) AJ6(-10.5,-12.5) AJ7(-9.5,-12.5) AJ8(-8.5,-12.5) AJ9(-7.5,-12.5) AJ10(-6.5,-12.5) AJ11(-5.5,-12.5) AJ12(-4.5,-12.5) AJ13(-3.5,-12.5) AJ14(-2.5,-12.5) AJ15(-1.5,-12.5) AJ16(-0.5,-12.5) AJ17(0.5,-12.5) AJ18(1.5,-12.5) AJ19(2.5,-12.5) AJ20(3.5,-12.5) AJ21(4.5,-12.5) AJ22(5.5,-12.5) AJ23(6.5,-12.5) AJ24(7.5,-12.5) AJ25(8.5,-12.5) AJ26(9.5,-12.5) AJ27(10.5,-12.5) AJ28(11.5,-12.5) AJ29(12.5,-12.5) AJ30(13.5,-12.5) AJ31(14.5,-12.5) AJ32(15.5,-12.5) AK2(-14.5,-13.5) AK3(-13.5,-13.5) AK4(-12.5,-13.5) AK5(-11.5,-13.5) AK6(-10.5,-13.5) AK7(-9.5,-13.5) AK8(-8.5,-13.5) AK9(-7.5,-13.5) AK10(-6.5,-13.5) AK11(-5.5,-13.5) AK12(-4.5,-13.5) AK13(-3.5,-13.5) AK14(-2.5,-13.5) AK15(-1.5,-13.5) AK16(-0.5,-13.5) AK17(0.5,-13.5) AK18(1.5,-13.5) AK19(2.5,-13.5) AK20(3.5,-13.5) AK21(4.5,-13.5) AK22(5.5,-13.5) AK23(6.5,-13.5) AK24(7.5,-13.5) AK25(8.5,-13.5) AK26(9.5,-13.5) AK27(10.5,-13.5) AK28(11.5,-13.5) AK29(12.5,-13.5) AK30(13.5,-13.5) AK31(14.5,-13.5) AL3(-13.5,-14.5) AL4(-12.5,-14.5) AL5(-11.5,-14.5) AL6(-10.5,-14.5) AL7(-9.5,-14.5) AL8(-8.5,-14.5) AL9(-7.5,-14.5) AL10(-6.5,-14.5) AL11(-5.5,-14.5) AL12(-4.5,-14.5) AL13(-3.5,-14.5) AL14(-2.5,-14.5) AL15(-1.5,-14.5) AL16(-0.5,-14.5) AL17(0.5,-14.5) AL18(1.5,-14.5) AL19(2.5,-14.5) AL20(3.5,-14.5) AL21(4.5,-14.5) AL22(5.5,-14.5) AL23(6.5,-14.5) AL24(7.5,-14.5) AL25(8.5,-14.5) AL26(9.5,-14.5) AL27(10.5,-14.5) AL28(11.5,-14.5) AL29(12.5,-14.5) AL30(13.5,-14.5) AM4(-12.5,-15.5) AM5(-11.5,-15.5) AM6(-10.5,-15.5) AM7(-9.5,-15.5) AM8(-8.5,-15.5) AM9(-7.5,-15.5) AM10(-6.5,-15.5) AM11(-5.5,-15.5) AM12(-4.5,-15.5) AM13(-3.5,-15.5) AM14(-2.5,-15.5) AM15(-1.5,-15.5) AM16(-0.5,-15.5) AM17(0.5,-15.5) AM18(1.5,-15.5) AM19(2.5,-15.5) AM20(3.5,-15.5) AM21(4.5,-15.5) AM22(5.5,-15.5) AM23(6.5,-15.5) AM24(7.5,-15.5) AM25(8.5,-15.5) AM26(9.5,-15.5) AM27(10.5,-15.5) AM28(11.5,-15.5) AM29(12.5,-15.5) B3(-13.5,14.5) B4(-12.5,14.5) B5(-11.5,14.5) B6(-10.5,14.5) B7(-9.5,14.5) B8(-8.5,14.5) B9(-7.5,14.5) B10(-6.5,14.5) B11(-5.5,14.5) B12(-4.5,14.5) B13(-3.5,14.5) B14(-2.5,14.5) B15(-1.5,14.5) B16(-0.5,14.5) B17(0.5,14.5) B18(1.5,14.5) B19(2.5,14.5) B20(3.5,14.5) B21(4.5,14.5) B22(5.5,14.5) B23(6.5,14.5) B24(7.5,14.5) B25(8.5,14.5) B26(9.5,14.5) B27(10.5,14.5) B28(11.5,14.5) B29(12.5,14.5) B30(13.5,14.5) C2(-14.5,13.5) C3(-13.5,13.5) C4(-12.5,13.5) C5(-11.5,13.5) C6(-10.5,13.5) C7(-9.5,13.5) C8(-8.5,13.5) C9(-7.5,13.5) C10(-6.5,13.5) C11(-5.5,13.5) C12(-4.5,13.5) C13(-3.5,13.5) C14(-2.5,13.5) C15(-1.5,13.5) C16(-0.5,13.5) C17(0.5,13.5) C18(1.5,13.5) C19(2.5,13.5) C20(3.5,13.5) C21(4.5,13.5) C22(5.5,13.5) C23(6.5,13.5) C24(7.5,13.5) C25(8.5,13.5) C26(9.5,13.5) C27(10.5,13.5) C28(11.5,13.5) C29(12.5,13.5) C30(13.5,13.5) C31(14.5,13.5) D1(-15.5,12.5) D2(-14.5,12.5) D3(-13.5,12.5) D4(-12.5,12.5) D5(-11.5,12.5) D6(-10.5,12.5) D7(-9.5,12.5) D8(-8.5,12.5) D9(-7.5,12.5) D10(-6.5,12.5) D11(-5.5,12.5) D12(-4.5,12.5) D13(-3.5,12.5) D14(-2.5,12.5) D15(-1.5,12.5) D16(-0.5,12.5) D17(0.5,12.5) D18(1.5,12.5) D19(2.5,12.5) D20(3.5,12.5) D21(4.5,12.5) D22(5.5,12.5) D23(6.5,12.5) D24(7.5,12.5) D25(8.5,12.5) D26(9.5,12.5) D27(10.5,12.5) D28(11.5,12.5) D29(12.5,12.5) D30(13.5,12.5) D31(14.5,12.5) D32(15.5,12.5) E1(-15.5,11.5) E2(-14.5,11.5) E3(-13.5,11.5) E4(-12.5,11.5) E5(-11.5,11.5) E6(-10.5,11.5) E7(-9.5,11.5) E8(-8.5,11.5) E9(-7.5,11.5) E10(-6.5,11.5) E11(-5.5,11.5) E12(-4.5,11.5) E13(-3.5,11.5) E14(-2.5,11.5) E15(-1.5,11.5) E16(-0.5,11.5) E17(0.5,11.5) E18(1.5,11.5) E19(2.5,11.5) E20(3.5,11.5) E21(4.5,11.5) E22(5.5,11.5) E23(6.5,11.5) E24(7.5,11.5) E25(8.5,11.5) E26(9.5,11.5) E27(10.5,11.5) E28(11.5,11.5) E29(12.5,11.5) E30(13.5,11.5) E31(14.5,11.5) E32(15.5,11.5) F1(-15.5,10.5) F2(-14.5,10.5) F3(-13.5,10.5) F4(-12.5,10.5) F5(-11.5,10.5) F6(-10.5,10.5) F7(-9.5,10.5) F8(-8.5,10.5) F9(-7.5,10.5) F10(-6.5,10.5) F11(-5.5,10.5) F12(-4.5,10.5) F13(-3.5,10.5) F14(-2.5,10.5) F15(-1.5,10.5) F16(-0.5,10.5) F17(0.5,10.5) F18(1.5,10.5) F19(2.5,10.5) F20(3.5,10.5) F21(4.5,10.5) F22(5.5,10.5) F23(6.5,10.5) F24(7.5,10.5) F25(8.5,10.5) F26(9.5,10.5) F27(10.5,10.5) F28(11.5,10.5) F29(12.5,10.5) F30(13.5,10.5) F31(14.5,10.5) F32(15.5,10.5) G1(-15.5,9.5) G2(-14.5,9.5) G3(-13.5,9.5) G4(-12.5,9.5) G5(-11.5,9.5) G6(-10.5,9.5) G7(-9.5,9.5) G8(-8.5,9.5) G9(-7.5,9.5) G10(-6.5,9.5) G11(-5.5,9.5) G12(-4.5,9.5) G13(-3.5,9.5) G14(-2.5,9.5) G15(-1.5,9.5) G16(-0.5,9.5) G17(0.5,9.5) G18(1.5,9.5) G19(2.5,9.5) G20(3.5,9.5) G21(4.5,9.5) G22(5.5,9.5) G23(6.5,9.5) G24(7.5,9.5) G25(8.5,9.5) G26(9.5,9.5) G27(10.5,9.5) G28(11.5,9.5) G29(12.5,9.5) G30(13.5,9.5) G31(14.5,9.5) G32(15.5,9.5) H1(-15.5,8.5) H2(-14.5,8.5) H3(-13.5,8.5) H4(-12.5,8.5) H5(-11.5,8.5) H6(-10.5,8.5) H7(-9.5,8.5) H8(-8.5,8.5) H9(-7.5,8.5) H10(-6.5,8.5) H11(-5.5,8.5) H12(-4.5,8.5) H13(-3.5,8.5) H14(-2.5,8.5) H15(-1.5,8.5) H16(-0.5,8.5) H17(0.5,8.5) H18(1.5,8.5) H19(2.5,8.5) H20(3.5,8.5) H21(4.5,8.5) H22(5.5,8.5) H23(6.5,8.5) H24(7.5,8.5) H25(8.5,8.5) H26(9.5,8.5) H27(10.5,8.5) H28(11.5,8.5) H29(12.5,8.5) H30(13.5,8.5) H31(14.5,8.5) H32(15.5,8.5) J1(-15.5,7.5) J2(-14.5,7.5) J3(-13.5,7.5) J4(-12.5,7.5) J5(-11.5,7.5) J6(-10.5,7.5) J7(-9.5,7.5) J8(-8.5,7.5) J9(-7.5,7.5) J10(-6.5,7.5) J11(-5.5,7.5) J12(-4.5,7.5) J13(-3.5,7.5) J14(-2.5,7.5) J15(-1.5,7.5) J16(-0.5,7.5) J17(0.5,7.5) J18(1.5,7.5) J19(2.5,7.5) J20(3.5,7.5) J21(4.5,7.5) J22(5.5,7.5) J23(6.5,7.5) J24(7.5,7.5) J25(8.5,7.5) J26(9.5,7.5) J27(10.5,7.5) J28(11.5,7.5) J29(12.5,7.5) J30(13.5,7.5) J31(14.5,7.5) J32(15.5,7.5) K1(-15.5,6.5) K2(-14.5,6.5) K3(-13.5,6.5) K4(-12.5,6.5) K5(-11.5,6.5) K6(-10.5,6.5) K7(-9.5,6.5) K8(-8.5,6.5) K9(-7.5,6.5) K10(-6.5,6.5) K11(-5.5,6.5) K12(-4.5,6.5) K13(-3.5,6.5) K14(-2.5,6.5) K15(-1.5,6.5) K16(-0.5,6.5) K17(0.5,6.5) K18(1.5,6.5) K19(2.5,6.5) K20(3.5,6.5) K21(4.5,6.5) K22(5.5,6.5) K23(6.5,6.5) K24(7.5,6.5) K25(8.5,6.5) K26(9.5,6.5) K27(10.5,6.5) K28(11.5,6.5) K29(12.5,6.5) K30(13.5,6.5) K31(14.5,6.5) K32(15.5,6.5) L1(-15.5,5.5) L2(-14.5,5.5) L3(-13.5,5.5) L4(-12.5,5.5) L5(-11.5,5.5) L6(-10.5,5.5) L7(-9.5,5.5) L8(-8.5,5.5) L9(-7.5,5.5) L10(-6.5,5.5) L11(-5.5,5.5) L12(-4.5,5.5) L13(-3.5,5.5) L14(-2.5,5.5) L15(-1.5,5.5) L16(-0.5,5.5) L17(0.5,5.5) L18(1.5,5.5) L19(2.5,5.5) L20(3.5,5.5) L21(4.5,5.5) L22(5.5,5.5) L23(6.5,5.5) L24(7.5,5.5) L25(8.5,5.5) L26(9.5,5.5) L27(10.5,5.5) L28(11.5,5.5) L29(12.5,5.5) L30(13.5,5.5) L31(14.5,5.5) L32(15.5,5.5) M1(-15.5,4.5) M2(-14.5,4.5) M3(-13.5,4.5) M4(-12.5,4.5) M5(-11.5,4.5) M6(-10.5,4.5) M7(-9.5,4.5) M8(-8.5,4.5) M9(-7.5,4.5) M10(-6.5,4.5) M11(-5.5,4.5) M12(-4.5,4.5) M13(-3.5,4.5) M14(-2.5,4.5) M15(-1.5,4.5) M16(-0.5,4.5) M17(0.5,4.5) M18(1.5,4.5) M19(2.5,4.5) M20(3.5,4.5) M21(4.5,4.5) M22(5.5,4.5) M23(6.5,4.5) M24(7.5,4.5) M25(8.5,4.5) M26(9.5,4.5) M27(10.5,4.5) M28(11.5,4.5) M29(12.5,4.5) M30(13.5,4.5) M31(14.5,4.5) M32(15.5,4.5) N1(-15.5,3.5) N2(-14.5,3.5) N3(-13.5,3.5) N4(-12.5,3.5) N5(-11.5,3.5) N6(-10.5,3.5) N7(-9.5,3.5) N8(-8.5,3.5) N9(-7.5,3.5) N10(-6.5,3.5) N11(-5.5,3.5) N12(-4.5,3.5) N13(-3.5,3.5) N14(-2.5,3.5) N15(-1.5,3.5) N16(-0.5,3.5) N17(0.5,3.5) N18(1.5,3.5) N19(2.5,3.5) N20(3.5,3.5) N21(4.5,3.5) N22(5.5,3.5) N23(6.5,3.5) N24(7.5,3.5) N25(8.5,3.5) N26(9.5,3.5) N27(10.5,3.5) N28(11.5,3.5) N29(12.5,3.5) N30(13.5,3.5) N31(14.5,3.5) N32(15.5,3.5) P1(-15.5,2.5) P2(-14.5,2.5) P3(-13.5,2.5) P4(-12.5,2.5) P5(-11.5,2.5) P6(-10.5,2.5) P7(-9.5,2.5) P8(-8.5,2.5) P9(-7.5,2.5) P10(-6.5,2.5) P11(-5.5,2.5) P12(-4.5,2.5) P13(-3.5,2.5) P14(-2.5,2.5) P15(-1.5,2.5) P16(-0.5,2.5) P17(0.5,2.5) P18(1.5,2.5) P19(2.5,2.5) P20(3.5,2.5) P21(4.5,2.5) P22(5.5,2.5) P23(6.5,2.5) P24(7.5,2.5) P25(8.5,2.5) P26(9.5,2.5) P27(10.5,2.5) P28(11.5,2.5) P29(12.5,2.5) P30(13.5,2.5) P31(14.5,2.5) P32(15.5,2.5) R1(-15.5,1.5) R2(-14.5,1.5) R3(-13.5,1.5) R4(-12.5,1.5) R5(-11.5,1.5) R6(-10.5,1.5) R7(-9.5,1.5) R8(-8.5,1.5) R9(-7.5,1.5) R10(-6.5,1.5) R11(-5.5,1.5) R12(-4.5,1.5) R13(-3.5,1.5) R14(-2.5,1.5) R15(-1.5,1.5) R16(-0.5,1.5) R17(0.5,1.5) R18(1.5,1.5) R19(2.5,1.5) R20(3.5,1.5) R21(4.5,1.5) R22(5.5,1.5) R23(6.5,1.5) R24(7.5,1.5) R25(8.5,1.5) R26(9.5,1.5) R27(10.5,1.5) R28(11.5,1.5) R29(12.5,1.5) R30(13.5,1.5) R31(14.5,1.5) R32(15.5,1.5) T1(-15.5,0.5) T2(-14.5,0.5) T3(-13.5,0.5) T4(-12.5,0.5) T5(-11.5,0.5) T6(-10.5,0.5) T7(-9.5,0.5) T8(-8.5,0.5) T9(-7.5,0.5) T10(-6.5,0.5) T11(-5.5,0.5) T12(-4.5,0.5) T13(-3.5,0.5) T14(-2.5,0.5) T15(-1.5,0.5) T16(-0.5,0.5) T17(0.5,0.5) T18(1.5,0.5) T19(2.5,0.5) T20(3.5,0.5) T21(4.5,0.5) T22(5.5,0.5) T23(6.5,0.5) T24(7.5,0.5) T25(8.5,0.5) T26(9.5,0.5) T27(10.5,0.5) T28(11.5,0.5) T29(12.5,0.5) T30(13.5,0.5) T31(14.5,0.5) T32(15.5,0.5) U1(-15.5,-0.5) U2(-14.5,-0.5) U3(-13.5,-0.5) U4(-12.5,-0.5) U5(-11.5,-0.5) U6(-10.5,-0.5) U7(-9.5,-0.5) U8(-8.5,-0.5) U9(-7.5,-0.5) U10(-6.5,-0.5) U11(-5.5,-0.5) U12(-4.5,-0.5) U13(-3.5,-0.5) U14(-2.5,-0.5) U15(-1.5,-0.5) U16(-0.5,-0.5) U17(0.5,-0.5) U18(1.5,-0.5) U19(2.5,-0.5) U20(3.5,-0.5) U21(4.5,-0.5) U22(5.5,-0.5) U23(6.5,-0.5) U24(7.5,-0.5) U25(8.5,-0.5) U26(9.5,-0.5) U27(10.5,-0.5) U28(11.5,-0.5) U29(12.5,-0.5) U30(13.5,-0.5) U31(14.5,-0.5) U32(15.5,-0.5) V1(-15.5,-1.5) V2(-14.5,-1.5) V3(-13.5,-1.5) V4(-12.5,-1.5) V5(-11.5,-1.5) V6(-10.5,-1.5) V7(-9.5,-1.5) V8(-8.5,-1.5) V9(-7.5,-1.5) V10(-6.5,-1.5) V11(-5.5,-1.5) V12(-4.5,-1.5) V13(-3.5,-1.5) V14(-2.5,-1.5) V15(-1.5,-1.5) V16(-0.5,-1.5) V17(0.5,-1.5) V18(1.5,-1.5) V19(2.5,-1.5) V20(3.5,-1.5) V21(4.5,-1.5) V22(5.5,-1.5) V23(6.5,-1.5) V24(7.5,-1.5) V25(8.5,-1.5) V26(9.5,-1.5) V27(10.5,-1.5) V28(11.5,-1.5) V29(12.5,-1.5) V30(13.5,-1.5) V31(14.5,-1.5) V32(15.5,-1.5) W1(-15.5,-2.5) W2(-14.5,-2.5) W3(-13.5,-2.5) W4(-12.5,-2.5) W5(-11.5,-2.5) W6(-10.5,-2.5) W7(-9.5,-2.5) W8(-8.5,-2.5) W9(-7.5,-2.5) W10(-6.5,-2.5) W11(-5.5,-2.5) W12(-4.5,-2.5) W13(-3.5,-2.5) W14(-2.5,-2.5) W15(-1.5,-2.5) W16(-0.5,-2.5) W17(0.5,-2.5) W18(1.5,-2.5) W19(2.5,-2.5) W20(3.5,-2.5) W21(4.5,-2.5) W22(5.5,-2.5) W23(6.5,-2.5) W24(7.5,-2.5) W25(8.5,-2.5) W26(9.5,-2.5) W27(10.5,-2.5) W28(11.5,-2.5) W29(12.5,-2.5) W30(13.5,-2.5) W31(14.5,-2.5) W32(15.5,-2.5) Y1(-15.5,-3.5) Y2(-14.5,-3.5) Y3(-13.5,-3.5) Y4(-12.5,-3.5) Y5(-11.5,-3.5) Y6(-10.5,-3.5) Y7(-9.5,-3.5) Y8(-8.5,-3.5) Y9(-7.5,-3.5) Y10(-6.5,-3.5) Y11(-5.5,-3.5) Y12(-4.5,-3.5) Y13(-3.5,-3.5) Y14(-2.5,-3.5) Y15(-1.5,-3.5) Y16(-0.5,-3.5) Y17(0.5,-3.5) Y18(1.5,-3.5) Y19(2.5,-3.5) Y20(3.5,-3.5) Y21(4.5,-3.5) Y22(5.5,-3.5) Y23(6.5,-3.5) Y24(7.5,-3.5) Y25(8.5,-3.5) Y26(9.5,-3.5) Y27(10.5,-3.5) Y28(11.5,-3.5) Y29(12.5,-3.5) Y30(13.5,-3.5) Y31(14.5,-3.5) Y32(15.5,-3.5)
